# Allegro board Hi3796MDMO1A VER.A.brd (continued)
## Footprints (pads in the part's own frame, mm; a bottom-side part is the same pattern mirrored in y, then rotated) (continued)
SEN3-100C
  rect 1.27x1.27 hole 0.813: 1(-2.54,0)
  round 1.27 hole 0.813: 2(0,0) 3(2.54,0)
SGM8903
  rect 0.356x1.524 smd: 1(-1.95,-2.921) 2(-1.3,-2.921) 3(-0.65,-2.921) 4(0,-2.921) 5(0.65,-2.921) 6(1.3,-2.921) 7(1.95,-2.921) 8(1.95,2.921) 9(1.3,2.921) 10(0.65,2.921) 11(0,2.921) 12(-0.65,2.921) 13(-1.3,2.921) 14(-1.95,2.921)
SIP-1P
  round 1.651 hole 0.914: 1(0,0)
SIP-6P-100
  rect 1.524x1.524 hole 1.016: 1(6.25,0)
  round 1.524 hole 1.016: 2(3.75,0) 3(1.25,0) 4(-1.25,0) 5(-3.75,0) 6(-6.25,0)
SL0402
  rect 0.483x0.508 smd: 1(-0.394,0) 2(0.394,0)
SL0603
  rect 0.711x0.813 smd: 1(-0.74,0) 2(0.74,0)
SL0805
  rect 0.94x1.27 smd: 1(-0.851,0) 2(0.851,0)
SL1210
  rect 1.295x2.413 smd: 1(-1.346,0) 2(1.346,0)
SOP14-50-150
  rect 0.635x1.905 smd: 1(-3.81,-2.667) 2(-2.54,-2.667) 3(-1.27,-2.667) 4(0,-2.667) 5(1.27,-2.667) 6(2.54,-2.667) 7(3.81,-2.667) 8(3.81,2.667) 9(2.54,2.667) 10(1.27,2.667) 11(0,2.667) 12(-1.27,2.667) 13(-2.54,2.667) 14(-3.81,2.667)
SOP48-20-720B
  rect 0.254x1.473 smd: 1(-5.75,-9.802) 2(-5.25,-9.802) 3(-4.75,-9.802) 4(-4.25,-9.802) 5(-3.75,-9.802) 6(-3.25,-9.802) 7(-2.75,-9.802) 8(-2.25,-9.802) 9(-1.75,-9.802) 10(-1.25,-9.802) 11(-0.75,-9.802) 12(-0.25,-9.802) 13(0.25,-9.802) 14(0.75,-9.802) 15(1.25,-9.802) 16(1.75,-9.802) 17(2.25,-9.802) 18(2.75,-9.802) 19(3.25,-9.802) 20(3.75,-9.802) 21(4.25,-9.802) 22(4.75,-9.802) 23(5.25,-9.802) 24(5.75,-9.802) 25(5.75,9.802) 26(5.25,9.802) 27(4.75,9.802) 28(4.25,9.802) 29(3.75,9.802) 30(3.25,9.802) 31(2.75,9.802) 32(2.25,9.802) 33(1.75,9.802) 34(1.25,9.802) 35(0.75,9.802) 36(0.25,9.802) 37(-0.25,9.802) 38(-0.75,9.802) 39(-1.25,9.802) 40(-1.75,9.802) 41(-2.25,9.802) 42(-2.75,9.802) 43(-3.25,9.802) 44(-3.75,9.802) 45(-4.25,9.802) 46(-4.75,9.802) 47(-5.25,9.802) 48(-5.75,9.802)
SOT23
  rect 1.016x1.27 smd: 1(-1.016,-1.143) 2(1.016,-1.143) 3(0,1.143)
SOT23-5
  rect 0.711x1.016 smd: 1(-0.95,-1.3) 2(0,-1.3) 3(0.95,-1.3) 4(0.95,1.3) 5(-0.95,1.3)
SOT23_5
  rect 0.635x1.27 smd: 1(-0.95,-1.2) 2(0,-1.2) 3(0.95,-1.2) 4(0.95,1.2) 5(-0.95,1.2)
SOT23_6
  rect 0.635x1.397 smd: 1(-0.95,-1.2) 2(0,-1.2) 3(0.95,-1.2) 4(0.95,1.2) 5(0,1.2) 6(-0.95,1.2)
SOT23A-6L
  rect 0.635x1.27 smd: 1(-0.95,-1.25) 2(0,-1.25) 3(0.95,-1.25) 4(0.95,1.25) 5(0,1.25) 6(-0.95,1.25)
SOT223A
  rect 1.016x2.032 smd: 1(-2.286,-3.15) 2(0,-3.15) 3(2.286,-3.15)
  rect 3.302x2.032 smd: 4(0,3.15)
SPSW6-T
  rect 1.829x1.118 smd: 1(-3.1,1.85) 2(3.1,1.85) 3(-3.1,-1.85) 4(3.1,-1.85)
  rect 1.397x0.61 smd: 5(0,2.5) 6(0,-2.5)
SR0402
  rect 0.508x0.508 smd: 1(-0.406,0) 2(0.406,0)
SR0603
  rect 0.711x0.813 smd: 1(-0.737,0) 2(0.737,0)
SR0805
  rect 0.838x1.143 smd: 1(-0.927,0) 2(0.927,0)
SR1206
  rect 1.295x1.6 smd: 1(-1.346,0) 2(1.346,0)
STFM16-50-285
  rect 0.635x1.905 smd: 1(-4.445,-4.381) 2(-3.175,-4.381) 3(-1.905,-4.381) 4(-0.635,-4.381) 5(0.635,-4.381) 6(1.905,-4.381) 7(3.175,-4.381) 8(4.445,-4.381) 9(4.445,4.381) 10(3.175,4.381) 11(1.905,4.381) 12(0.635,4.381) 13(-0.635,4.381) 14(-1.905,4.381) 15(-3.175,4.381) 16(-4.445,4.381)
SWPA4020S
  rect 1.905x3.683 smd: 1(-1.55,0) 2(1.55,0)
SWPA4030S
  rect 1.905x3.683 smd: 1(-1.55,0) 2(1.55,0)
SWPA5040S
  rect 1.397x4.191 smd: 1(-1.85,0) 2(1.85,0)
SX2-1205
  rect 4.826x1.524 smd: 1(-4.85,0) 2(4.85,0)
TO-252
  rect 1.27x2.032 smd: 1(-2.285,-3.375) 2(0,-3.375) 3(2.285,-3.375)
  rect 5.715x5.842 smd: 4(0,3.375)
TSSOP16EP
  rect 0.356x1.651 smd: 1(-2.275,-2.9) 2(-1.625,-2.9) 3(-0.975,-2.9) 4(-0.325,-2.9) 5(0.325,-2.9) 6(0.975,-2.9) 7(1.625,-2.9) 8(2.275,-2.9) 9(2.275,2.9) 10(1.625,2.9) 11(0.975,2.9) 12(0.325,2.9) 13(-0.325,2.9) 14(-0.975,2.9) 15(-1.625,2.9) 16(-2.275,2.9)
  rect 4.191x3.302 smd: 17(0,0)
TSW4-RG-C
  round 1.524 hole 1.016: 1(0,0) 2(4.5,0)
  round 2.032 hole 1.321: 3(-1.25,2.5) 4(5.75,2.5)
unnamed#2
  round 1.016 hole 1.016 unplated: (-3,1.13) (-1.5,1.13) (0,1.13) (1.5,1.13) (3,1.13)
USB3_0_9P_DIP_MAINSUPER
  round 1.245 hole 0.762: 1(0,0) 2(2.5,0) 3(4.5,0) 4(7,0) 5(7.5,1.5) 6(5.5,1.5) 7(3.5,1.5) 8(1.5,1.5) 9(-0.5,1.5)
  round 2.896 hole 2.413: 10(-3.07,-2) 11(10.07,-2)
USB4-1415
  rect 1.27x1.524 hole 1.016: 1(0,0)
  oval 1.27x1.524 hole 1.016: 2(2.5,0) 3(4.5,0) 4(7,0)
  round 3.048 hole 2.286: 5(-3.07,-2.71) 6(10.07,-2.71)
VAF6-1107
  round 1.016 hole 1.016 unplated: (1.7,2.3) (8.5,2.3)
  round 0 smd: 1(4.503,2.3)
  rect 2.159x1.626 hole 1.321x0.61: 2(0,0)
  oval 2.159x1.626 hole 1.321x0.61: 3(3,0)
  oval 2.337x1.626 hole 1.321x0.61: 4(7,0.2) 5(8.6,4.6) 6(0,5.6)
WBC0104-49T
  oval 0.762x1.143 hole 0.508: 1(0,0) 2(1.25,0) 3(2.5,0) 4(3.75,0)
WBC0119-20R-A
  round 1.092 hole 1.092 unplated: (-2.5,2.745) (2.5,2.745)
  rect 0.254x2.591 smd: 1(4.5,5.155) 2(4,5.155) 3(3.5,5.155) 4(3,5.155) 5(2.5,5.155) 6(2,5.155) 7(1.5,5.155) 8(1,5.155) 9(0.5,5.155) 10(0,5.155) 11(-0.5,5.155) 12(-1,5.155) 13(-1.5,5.155) 14(-2,5.155) 15(-2.5,5.155) 16(-3,5.155) 17(-3.5,5.155) 18(-4,5.155) 19(-4.5,5.155)
  oval 1.524x3.302 hole 0.914x2.667: 20(-7.25,4.395) 21(7.25,4.395)
  oval 1.524x2.794 hole 0.914x2.083: 22(-7.25,-1.565) 23(7.25,-1.565)
X288
  rect 1.651x1.27 smd: 1(-1.15,-0.85) 2(1.15,-0.85) 3(1.15,0.85) 4(-1.15,0.85)

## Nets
1V1_CORE: C19.1 C51.1 C82.2 C90.1 C107.1 C120.1 C121.1 C127.1 C128.1 C173.1 C189.1 C192.1 C193.1 L3.2 LB11.1 LB12.2 LB21.1 LB31.1 R101.2 U10.K14 U10.K15 U10.K16 U10.K17 U10.L14 U10.L15 U10.M14 U10.M15 U10.N14 U10.N15 U10.P14 U10.P15 U10.R11 U10.R14 U10.R15 U10.T11 U10.T14 U10.T15 U10.U11 U10.U12 U10.U13 U10.U14 U10.U15 U10.V11 U10.V12 U10.V13 U10.V14 U10.V15 U10.V16
1V1_CPU: C31.1 C35.1 C41.1 C76.2 C116.1 C132.1 C135.1 C138.1 C161.1 C242.1 C243.1 C257.1 L4.2 R53.2 U10.L21 U10.M19 U10.M21 U10.M22 U10.N18 U10.N19 U10.N22 U10.P18 U10.P19 U10.P22 U10.R19 U10.R21
1V2_ADC_S: C125.1 C209.1 LB13.2 U2.33
1V2_APLL_S: C126.1 C210.1 LB15.2 U2.28
1V2_DVDD_S: C109.1 C110.1 C113.1 C117.1 C205.1 LB10.2 U2.7 U2.17 U2.25 U2.42
1V5_DDR3: C20.1 C34.1 C42.1 C68.1 C84.2 C94.1 C96.1 C97.1 C98.1 C99.1 C100.1 C101.1 C102.1 C106.1 C137.1 C152.1 C179.1 C180.1 C203.1 C206.1 C207.1 C208.1 C211.1 C212.1 C213.1 C214.1 C215.1 C216.1 C218.1 C219.1 C220.1 C222.1 C223.1 C227.1 C228.1 C229.1 C230.1 C232.1 C233.1 C237.1 C238.1 C239.1 C240.1 C258.1 C315.1 C319.1 L2.2 R26.2 R54.1 R78.1 R120.2 R158.1 R161.1 U3.A1 U3.A8 U3.B2 U3.C1 U3.C9 U3.D2 U3.D9 U3.E9 U3.F1 U3.G7 U3.H2 U3.H9 U3.K2 U3.K8 U3.N1 U3.N9 U3.R1 U3.R9 U6.A1 U6.A8 U6.B2 U6.C1 U6.C9 U6.D2 U6.D9 U6.E9 U6.F1 U6.G7 U6.H2 U6.H9 U6.K2 U6.K8 U6.N1 U6.N9 U6.R1 U6.R9 U10.AA7 U10.AB6 U10.AB7 U10.AB8 U10.AB9 U10.AB10 U10.AB11 U10.AB12 U10.AB13 U10.AB14 U10.AB15 U10.AC5 U10.AC6 U10.AC7 U10.AC8 U10.AC12 U10.AD4 U10.AD5 U10.AD6 U10.AD7 U10.AE4 U10.AE5 U10.AE6 U10.N7 U10.N9 U10.P7 U10.P9 U10.R6 U10.R7 U10.T7 U10.U7 U10.V7 U10.W7 U10.W9 U10.Y7 U10.Y9 U10.Y11 U10.Y12
3V3: C13.1 C67.1 C108.1 C112.2 C187.1 C191.1 J18.4 L5.2 Q13.2 R34.1 R41.1 R42.2 R88.2 R100.2 R122.1 R129.1 R135.1 R136.2 R140.2 R147.1 R178.1 U10.AD23 U10.AD24
3V3_AVDD_S: C86.1 C201.1 LB5.2 R69.1 U2.30
3V3_DVDD_S: C73.1 C74.1 C75.1 C81.1 C200.1 LB4.2 R103.2 U2.4 U2.11 U2.19 U2.45
3V3_MOS: C15.1 C88.1 C89.1 C92.1 C157.1 C197.1 C198.1 C199.1 C202.1 C245.1 C348.1 D9.2 D12.2 D14.2 J7.5 J25.10 J25.12 L21.1 LB1.2 LB3.1 LB4.1 LB5.1 LB7.2 LB8.2 LB14.1 LB17.1 LB18.1 LB20.1 LB22.1 LB35.1 Q13.3 Q14.1 Q15.2 R35.1 R65.1 R66.1 R77.1 R91.2 R96.2 R104.1 R108.1 R109.1 R116.2 R125.2 R155.1 R218.1 R219.1 R267.1 R271.1 U10.AA24 U10.AB24 U10.E13 U10.E14 U10.E19 U10.G5 U10.H24 U10.K24 U10.L24 U10.Y24 U12.3
3V3_MOS_FLASH: C22.1 C36.1 C47.1 C48.1 C93.1 C142.1 C143.1 C162.1 C323.1 C324.1 D14.1 R12.1 R25.1 R29.1 R58.1 R109.2 R111.1 R176.1 R177.1 R188.1 R189.1 R202.1 R203.1 R212.1 R215.1 U19.1(TP-1) U19.12(TP-12) U19.24(TP-24) U19.34(TP-34) U19.37(TP-37) U22.AA3 U22.AA5 U22.K6 U22.M6 U22.N5 U22.T10 U22.U9 U22.W4 U22.Y4
3V3_RF: C57.1 C144.1 C169.2 C195.2 C296.1 L21.2 R112.2 U14.2(TP-2) U14.4(TP-4) U34.23 U34.28
3V3_SD: C28.1 C61.1 J13.4 Q15.3 R210.1
3V3_WIFI: C60.1 C196.1 LB3.2 U7.5
5V0: C2.1 C4.1 C6.1 C25.1 C26.1 C27.1 C46.1 C53.1 C59.1 C65.1 C69.1 C83.1 C114.1 C184.1 L8.2 Q8.2 R6.1 R48.1 R144.1 R191.2 U1.4 U11.4 U13.4 U15.4
5V0_MOS: C50.1 C56.1 C87.2 C347.1 D13.2 J7.3 LB33.1 LB47.1 LB49.1 Q8.3 R113.2 R179.1 R220.2 U16.1 U24.14 U26.1
5V0_MOS_HDMI: C150.1 D13.1 J26.18 R186.2 R187.2 U4.5
5V0_SPDIF: C159.1 LB49.2 U9.2(TP-2)
12V0_MOS: C63.1 C136.1 C183.1 J7.1 L7.1 Q3.3 R117.1 R121.1 U17.3
12V0_PWR: C44.1 C91.1 C111.1 C133.1 C160.1 LB6.2 Q3.2 R95.1 R98.1 R110.1 U18.3
AVDD11_PLL012: C12.1 C185.1 LB21.2 U10.U18 U10.U19
AVDD11_USB3: C16.1 C119.1 LB11.2 U10.AA19 U10.Y18 U10.Y19
AVDD33_ADAC: C188.1 LB35.2 U10.E22
AVDD33_PLL01: C14.1 C141.1 LB22.2 U10.W21 U10.Y22
AVDD33_USB2: C3.1 LB17.2 U10.U24
AVDD33_USB3: C18.1 LB18.2 U10.AD20 U10.AD21
DVDD11_LDO1_OUT: C255.2 U10.AA21
GND: C1.2 C2.2 C3.2 C4.2 C5.2 C7.2 C8.2 C9.2 C10.2 C11.2 C12.2 C13.2 C14.2 C15.2 C16.2 C17.2 C18.2 C19.2 C20.2 C21.2 C22.2 C23.2 C24.2 C25.2 C26.2 C27.2 C28.2 C29.2 C30.2 C31.2 C33.1 C34.2 C35.2 C36.2 C37.2 C38.2 C39.2 C40.2 C41.2 C42.2 C43.2 C44.2 C45.2 C46.2 C47.2 C48.2 C49.2 C50.2 C51.2 C52.2 C53.2 C56.2 C57.2 C58.2 C59.2 C60.2 C61.2 C62.2 C63.2 C65.2 C66.2 C67.2 C68.2 C69.2 C71.2 C72.2 C73.2 C74.2 C75.2 C77.2 C78.2 C79.2 C81.2 C83.2 C85.2 C86.2 C87.1 C88.2 C89.2 C90.2 C91.2 C92.2 C93.2 C94.2 C95.2 C96.2 C97.2 C98.2 C99.2 C100.2 C101.2 C102.2 C103.2 C104.2 C105.2 C106.2 C107.2 C108.2 C109.2 C110.2 C111.2 C113.2 C114.2 C115.2 C116.2 C117.2 C118.1 C119.2 C120.2 C121.2 C122.2 C123.2 C124.2 C125.2 C126.2 C127.2 C128.2 C130.2 C131.2 C132.2 C134.2 C135.2 C136.2 C137.2 C138.2 C140.2 C141.2 C142.2 C143.2 C144.2 C145.2 C146.2 C147.2 C148.2 C149.2 C150.2 C151.2 C152.2 C153.2 C154.2 C158.2 C159.2 C160.2 C161.2 C162.2 C163.1 C164.2 C165.2 C166.2 C167.2 C168.1 C169.1 C170.2 C171.1 C172.2 C173.2 C174.2 C176.2 C177.2 C179.2 C180.2 C181.2 C182.2 C183.2 C184.2 C185.2 C187.2 C188.2 C189.2 C190.2 C191.2 C192.2 C193.2 C194.2 C195.1 C196.2 C197.2 C198.2 C199.2 C200.2 C201.2 C202.2 C203.2 C204.2 C205.2 C206.2 C209.2 C210.2 C211.2 C212.2 C213.2 C214.2 C215.2 C216.2 C217.2 C218.2 C219.2 C220.2 C221.2 C225.1 C226.2 C227.2 C228.2 C229.2 C230.2 C232.2 C233.2 C237.2 C238.2 C239.2 C240.2 C241.2 C242.2 C243.2 C244.2 C245.2 C246.2 C248.2 C250.1 C251.2 C255.1 C257.2 C258.2 C264.2 C270.2 C271.2 C281.2 C287.2 C288.2 C289.2 C296.2 C297.2 C304.1 C305.1 C308.2 C310.2 C313.2 C314.2 C315.2 C316.2 C317.2 C319.2 C320.2 C323.2 C324.2 C334.2 C336.2 C339.2 C341.1 C342.1 C343.1 C344.1 C347.2 C348.2 C353.2 C354.2 C363.2 C364.2 C365.2 C414.2 C487.1 C489.2 C490.2 C491.2 C531.2 C532.2 C534.2 C535.2 C536.2 C537.2 C538.2 C545.2 D3.2 D4.2 D5.2 D6.2 D9.1 D10.2 D11.1 D15.2 J1.4 J3.1 J4.1 J5.1 J6.4 J6.5 J6.6 J7.2 J7.4 J7.6 J7.7 J7.8 J7.18 J7.20 J9.4 J9.5 J9.6 J12.4 J12.7 J12.10 J12.11 J13.6 J13.10 J13.11 J13.12 J13.13 J13.14 J13.15 J14.1 J14.2 J14.3 J14.4 J16.3 J16.4 J16.5 J16.6 J16.7 J16.8 J18.1 J26.2 J26.5 J26.8 J26.11 J26.17 J26.20 J26.21 J26.22 J26.23 J34.5 L16.1 LB9.2 LED1.2 M20.1 M20.2 M20.3 M20.4 M20.5 M20.6 M20.7 M20.8 M21.1 M21.2 M21.3 M21.4 M21.5 M21.6 M21.7 M21.8 M22.1 M22.2 M22.3 M22.4 M22.5 M22.6 M22.7 M22.8 M23.1 M23.2 M23.3 M23.4 M23.5 M23.6 M23.7 M23.8 Q2.2 Q4.2 Q5.2 Q6.2 Q7.2 Q9.2 R2.2 R3.2 R4.2 R8.1 R9.2 R32.1 R43.2 R44.1 R45.2 R46.1 R47.2 R52.2 R55.2 R56.1 R57.2 R59.2 R64.2 R71.1 R72.2 R82.1 R83.2 R84.2 R85.2 R86.2 R87.1 R89.2 R92.2 R94.2 R99.1 R102.1 R105.2 R106.1 R107.2 R110.2 R111.2 R115.1 R123.2 R124.1 R126.1 R130.1 R131.2 R138.2 R141.2 R145.2 R146.2 R148.2 R149.2 R159.2 R160.2 R173.2 R183.2 R210.2 R229.2 R268.2 R269.2 R270.2 S9.2 S9.3 S9.4 S10.3 S10.4 S10.5 S10.6 U1.2 U2.29 U2.34 U2.47 U2.49 U3.A9 U3.B1 U3.B3 U3.B9 U3.D1 U3.D8 U3.E1 U3.E2 U3.E8 U3.F9 U3.G1 U3.G8 U3.G9 U3.J2 U3.J8 U3.M1 U3.M9 U3.P1 U3.P9 U3.T1 U3.T9 U4.2 U5.1 U5.4 U5.10 U5.14 U6.A9 U6.B1 U6.B3 U6.B9 U6.D1 U6.D8 U6.E1 U6.E2 U6.E8 U6.F9 U6.G1 U6.G8 U6.G9 U6.J2 U6.J8 U6.M1 U6.M9 U6.P1 U6.P9 U6.T1 U6.T9 U7.2 U8.3 U8.8 U9.3(TP-3) U10.A1 U10.A2 U10.A3 U10.A28 U10.AA1 U10.AA6 U10.AA18 U10.AA20 U10.AB2 U10.AB5 U10.AB16 U10.AB25 U10.AB27 U10.AC4 U10.AC9 U10.AC10 U10.AC11 U10.AC13 U10.AC14 U10.AC15 U10.AC16 U10.AC24 U10.AD3 U10.AD8 U10.AD9 U10.AD12 U10.AD14 U10.AD16 U10.AD17 U10.AD19 U10.AD22 U10.AD25 U10.AD26 U10.AE1 U10.AE3 U10.AE7 U10.AE8 U10.AE10 U10.AE18 U10.AE19 U10.AE21 U10.AE22 U10.AE23 U10.AE24 U10.AE25 U10.AE26 U10.AF2 U10.AF3 U10.AF4 U10.AF9 U10.AF14 U10.AF15 U10.AF16 U10.AF18 U10.AF19 U10.AF21 U10.AF22 U10.AF25 U10.AG1 U10.AG2 U10.AG5 U10.AG7 U10.AG11 U10.AG13 U10.AG28 U10.AH1 U10.AH2 U10.AH4 U10.AH6 U10.AH10 U10.AH12 U10.AH27 U10.AH28 U10.B2 U10.B3 U10.B4 U10.B14 U10.B25 U10.B26 U10.B27 U10.C3 U10.C4 U10.C6 U10.C7 U10.C8 U10.C10 U10.C14 U10.C16 U10.C18 U10.C19 U10.C20 U10.C22 U10.C24 U10.C25 U10.C26 U10.D4 U10.D6 U10.D7 U10.D8 U10.D10 U10.D14 U10.D16 U10.D18 U10.D19 U10.D20 U10.D22 U10.D24 U10.D25 U10.E2 U10.E4 U10.E5 U10.E8 U10.E9 U10.E11 U10.E12 U10.E15 U10.E18 U10.E20 U10.E21 U10.E23 U10.E24 U10.E25 U10.E26 U10.F1 U10.F3 U10.F4 U10.F5 U10.F25 U10.G4 U10.G8 U10.G12 U10.G13 U10.G14 U10.G17 U10.G19 U10.G21 U10.G24 U10.G25 U10.G26 U10.H1 U10.H2 U10.H4 U10.H5 U10.H12 U10.H13 U10.H14 U10.H17 U10.H18 U10.H21 U10.H22 U10.H25 U10.J3 U10.J4 U10.J5 U10.J21 U10.J22 U10.J24 U10.J25 U10.J26 U10.K3 U10.K11 U10.K13 U10.K18 U10.K19 U10.K21 U10.K22 U10.K25 U10.K26 U10.K27 U10.L1 U10.L2 U10.L3 U10.L4 U10.L5 U10.L11 U10.L12 U10.L13 U10.L16 U10.L17 U10.L18 U10.L19 U10.L22 U10.L25 U10.L26 U10.M3 U10.M4 U10.M5 U10.M6 U10.M11 U10.M12 U10.M13 U10.M16 U10.M17 U10.M18 U10.M24 U10.M25 U10.N3 U10.N6 U10.N11 U10.N12 U10.N13 U10.N16 U10.N17 U10.N24 U10.N25 U10.N26 U10.P2 U10.P6 U10.P11 U10.P12 U10.P13 U10.P16 U10.P17 U10.P24 U10.P25 U10.P26 U10.R1 U10.R3 U10.R5 U10.R9 U10.R12 U10.R13 U10.R16 U10.R17 U10.R18 U10.R22 U10.R24 U10.R26 U10.T3 U10.T4 U10.T6 U10.T12 U10.T13 U10.T16 U10.T17 U10.T18 U10.T19 U10.T22 U10.T24 U10.T25 U10.T26 U10.U6 U10.U9 U10.U16 U10.U17 U10.U21 U10.U22 U10.U25 U10.V2 U10.V3 U10.V5 U10.V6 U10.V9 U10.V17 U10.V18 U10.V19 U10.V21 U10.V24 U10.V25 U10.W1 U10.W5 U10.W6 U10.W22 U10.W24 U10.Y2 U10.Y4 U10.Y6 U10.Y10 U10.Y13 U10.Y15 U10.Y21 U10.Y25 U10.Y27 U11.2 U13.2 U15.2 U16.2 U17.1 U17.16 U17.17 U18.1 U19.2(TP-2) U19.13(TP-13) U19.23(TP-23) U19.25(TP-25) U19.36(TP-36) U19.48(TP-48) U22.AA4 U22.AA6 U22.K4 U22.M7 U22.P5 U22.R10 U22.U8 U22.Y2 U22.Y5 U23.3 U23.8 U24.2 U24.7 U26.2 U34.29 X2.2 X2.4
VCC_SCI: C29.1 C39.1 C40.1 J1.1 R124.2 R243.1 R302.2
VDD_AUDIO: C158.1 C320.1 R139.2 R174.1 R179.2 U5.9
3136_ADDR0: R3.1 U2.39
3136_ADDR1: R103.1 U2.38
3136_DISEQC_IN: Q6.3 R51.1 R116.1 U2.13
3136_DISEQC_OUT: R123.1 U2.12 U17.9
3136_FUNC_SEL: R4.1 U2.14
3136_HV_SEL: U2.18 U17.8
3136_I2C_SCL: C221.1 R108.2 U2.41 U10.D26
3136_I2C_SDA: C217.1 R104.2 U2.40 U10.C27
3136_IOUT_N: C307.2 U2.32
3136_IOUT_P: C303.2 U2.31
3136_LNB_EN: U2.21 U17.5
3136_QOUT_N: C186.2 U2.35
3136_QOUT_P: C306.2 U2.36
3136_RF_AGC: C37.1 R60.1 R127.2
3136_RSTN: C38.1 R83.1 U2.15 U10.C28
3136_TS_CLK: R10.2 U2.46
3136_TS_OUT0: R13.2 U2.48
3136_TS_SYNC: R226.2 U2.43
3136_TS_VAL: C176.1 R5.2 U2.44
3136_XIN: C172.1 R24.1 U2.23 X1.2
3136_XOUT: C174.1 R24.2 U2.22 X1.1
AC2012_SCL_T: R61.2 R65.2 U2.27
AC2012_SDA_T: R62.2 R66.2 U2.26
ADAC_VOUTL: C350.2 R138.1 U10.D23
ADAC_VOUTR: C351.1 R183.1 U10.C23
ADAC_VREF: C250.2 U10.G18
AUDIO_L: C339.1 J34.3 R119.2
AUDIO_R: C140.1 J34.2 R74.1
CORE_CTRL: R23.2 U10.E27
CPU_CTRL: R21.2 U10.E28
CVBS: C79.1 C80.1 L6.1 R9.1 U10.A25
CVBS_OUT: C17.1 C80.2 D9.3 J34.4 L6.2
DDR_ADDR0: U3.N3 U6.N3 U10.AF13
DDR_ADDR1: U3.P7 U6.P7 U10.AE12
DDR_ADDR2: U3.P3 U6.P3 U10.AD15
DDR_ADDR3: U3.N2 U6.N2 U10.AH15
DDR_ADDR4: U3.P8 U6.P8 U10.AD13
DDR_ADDR5: U3.P2 U6.P2 U10.AE16
DDR_ADDR6: U3.R8 U6.R8 U10.AF11
DDR_ADDR7: U3.R2 U6.R2 U10.AG15
DDR_ADDR8: U3.T8 U6.T8 U10.AG12
DDR_ADDR9: U3.R3 U6.R3 U10.AE17
DDR_ADDR10: U3.L7 U6.L7 U10.AE9
DDR_ADDR11: U3.R7 U6.R7 U10.AG10
DDR_ADDR12: U3.N7 U6.N7 U10.AE11
DDR_ADDR13: U3.T3 U6.T3 U10.AF17
DDR_ADDR14: U3.T7 U6.T7 U10.AF12
DDR_ADDR15: U3.M7 U6.M7 U10.AD11
DDR_BA0: U3.M2 U6.M2 U10.AH16
DDR_BA1: U3.N8 U6.N8 U10.AF10
DDR_BA2: U3.M3 U6.M3 U10.AE13
DDR_CASN: U3.K3 U6.K3 U10.AE15
DDR_CKE: R130.2 U3.K9 U6.K9 U10.AD10
DDR_CLK1N: R11.2 R15.2 R37.1 U3.K7 U6.K7
DDR_CLK1P: R11.1 R15.1 R36.1 U3.J7 U6.J7
DDR_CSN: U3.L2 U6.L2 U10.AH13
DDR_DM0: U3.E7 U10.R4
DDR_DM1: U3.D3 U10.T5
DDR_DM2: U6.E7 U10.AF1
DDR_DM3: U6.D3 U10.AE2
DDR_DQ0: U3.E3 U10.N4
DDR_DQ1: U3.F7 U10.V1
DDR_DQ2: U3.F2 U10.N1
DDR_DQ3: U3.F8 U10.W3
DDR_DQ4: U3.H3 U10.N5
DDR_DQ5: U3.H8 U10.Y3
DDR_DQ6: U3.G2 U10.N2
DDR_DQ7: U3.H7 U10.W2
DDR_DQ8: U3.D7 U10.U4
DDR_DQ9: U3.C3 U10.R2
DDR_DQ10: U3.C8 U10.U5
DDR_DQ11: U3.C2 U10.P3
DDR_DQ12: U3.A7 U10.V4
DDR_DQ13: U3.A2 U10.P4
DDR_DQ14: U3.B8 U10.W4
DDR_DQ15: U3.A3 U10.P5
DDR_DQ16: U6.E3 U10.AA5
DDR_DQ17: U6.F7 U10.AF6
DDR_DQ18: U6.F2 U10.AA2
DDR_DQ19: U6.F8 U10.AG6
DDR_DQ20: U6.H3 U10.Y5
DDR_DQ21: U6.H8 U10.AH7
DDR_DQ22: U6.G2 U10.AA3
DDR_DQ23: U6.H7 U10.AF7
DDR_DQ24: U6.D7 U10.AF5
DDR_DQ25: U6.C3 U10.AB1
DDR_DQ26: U6.C8 U10.AG4
DDR_DQ27: U6.C2 U10.AB3
DDR_DQ28: U6.A7 U10.AH3
DDR_DQ29: U6.A2 U10.AA4
DDR_DQ30: U6.B8 U10.AG3
DDR_DQ31: U6.A3 U10.AB4
DDR_DQS0N: U3.G3 U10.T1
DDR_DQS0P: U3.F3 U10.T2
DDR_DQS1N: U3.B7 U10.U3
DDR_DQS1P: U3.C7 U10.U2
DDR_DQS2N: U6.G3 U10.AC2
DDR_DQS2P: U6.F3 U10.AC3
DDR_DQS3N: U6.B7 U10.AD2
DDR_DQS3P: U6.C7 U10.AD1
DDR_ODT: U3.K1 U6.K1 U10.AG16
DDR_PLL: C11.1 C264.1 C270.1 LB7.1 U10.T9 U10.Y14
DDR_RASN: U3.J3 U6.J3 U10.AG17
DDR_RESETN: C313.1 C314.1 R26.1 U3.T2 U6.T2 U10.AG14
DDR_VREF_CA_A: C207.2 C289.1 R158.2 R159.1 U3.M8
DDR_VREF_CA_B: C222.2 C310.1 R107.1 R161.2 U6.M8
DDR_VREF_DQ_A: C208.2 C271.1 R54.2 R160.1 U3.H1
DDR_VREF_DQ_B: C223.2 C308.1 R78.2 R84.1 U6.H1
DDR_WEN: U3.L3 U6.L3 U10.AE14
DEMOD0_RESTN: J7.10 U10.L28
DEMOD0_SCL: J7.23 U10.G27
DEMOD0_SDA: J7.24 U10.G28
FE_1V1: C248.1 U10.K12
FE_3V3: C7.1 LB8.1 U10.E6 U10.E7
FE_REXT: R173.1 U10.G9
FUNC_SEL: R42.1 U10.AF26
HDMI_TX0N: J26.9 U8.2 U8.9 U10.D17
HDMI_TX0P: J26.7 U8.1 U8.10 U10.C17
HDMI_TX1N: J26.6 U10.B16 U23.5 U23.6
HDMI_TX1P: J26.4 U10.A16 U23.4 U23.7
HDMI_TX2N: J26.3 U10.D15 U23.2 U23.9
HDMI_TX2P: J26.1 U10.C15 U23.1 U23.10
HDMI_TX_1V1: C95.1 C164.1 C251.1 C281.1 LB12.1 U10.G16 U10.H16
HDMI_TX_3V3: C77.1 C122.1 LB1.1 U10.E16 U10.E17
HDMI_TX_CEC: J26.13 R184.2 U4.3 U10.A20
HDMI_TX_HOTPLUG: C149.1 J26.19 R8.2 U4.4 U10.D21
HDMI_TX_SCL: J26.15 R186.1 U4.1 U10.B20
HDMI_TX_SDA: J26.16 R187.1 U4.6 U10.C21
HDMI_TXCN: J26.12 U8.5 U8.6 U10.B18
HDMI_TXCP: J26.10 U8.4 U8.7 U10.A18
I2S0_BCLK: U10.D12
I2S0_DIN0: U10.D11
I2S0_DOUT0: U10.A10
I2S0_MCLK: U10.C11
I2S0_WS: U10.B10
IR_IN: D3.1 R140.1 U10.AG24
JTAG_SEL: R96.1 U10.F26
LED: U7.1
LED0_BASE: R67.2 R219.2 U10.C2
LED0_LINK_ACT: R185.2 R218.2 U10.B1
LED_CLK: R22.1 R57.1 R147.2 U10.AH23
LED_DATA: R31.1 R122.2 R148.1 U10.AG23
LED_KEY0: C21.1 R41.2 S9.1 U10.AF23
LNB_PWR: C58.1 C64.1 C78.1 C104.1 C155.2 C170.1 D17.2 D27.1 J16.2
LNB_PWR_B: C166.1 C287.1 C288.1 D27.2 R166.2
LOOPTHROUGH: C283.1 J16.1 R166.1
MUTE_CTRL: R90.1 U10.A22
NF_ALE_EMMC_PWREN: U10.W26 U19.17(TP-17)
NF_CLE: U10.V26 U19.16(TP-16)
NF_CSN0_EMMC_CMD: R212.2 U10.V28 U19.9(TP-9) U22.W5
NF_DQ0_EMMC_D0: R189.2 U10.Y28 U19.29(TP-29) U22.H3
NF_DQ1_EMMC_D1: R12.2 U10.Y26 U19.30(TP-30) U22.H4
NF_DQ2_EMMC_D2: R29.2 U10.AA26 U19.31(TP-31) U22.H5
NF_DQ3_EMMC_D3: R58.2 U10.AA25 U19.32(TP-32) U22.J2
NF_DQ4_EMMC_D4: R176.2 U10.AB28 U19.41(TP-41) U22.J3
NF_DQ5_EMMC_D5: R177.2 U10.AB26 U19.42(TP-42) U22.J4
NF_DQ6_EMMC_D6: R188.2 U10.AC26 U19.43(TP-43) U22.J5
NF_DQ7_EMMC_D7_BOOT_SEL0: R86.1 R202.2 U10.AC25 U19.44(TP-44) U22.J6
NF_RDY0_EMMC_RST: C115.1 R203.2 U10.U26 U19.7(TP-7) U22.U5
NF_REN_EMMC_CLK: U10.W25 U19.8(TP-8) U22.W6
NF_WEN_EMMC_DET: R56.2 U10.V27 U19.18(TP-18)
NF_WP: R89.1 R215.2 U19.19(TP-19)
REG2OUT: C130.1 C131.1 C225.2 C414.1 U34.1 U34.2 U34.5 U34.10 U34.25
RX+_PHY0: R50.1 U10.B6 U27.3 U27.6
RX-_PHY0: R18.1 U10.A6 U27.4 U27.5
SDIO0_CARD_DETECT: J13.9 R155.2 U10.J2
SDIO0_CCLK_OUT: J13.5 R16.1
SDIO0_CCMD: J13.3 R153.2 U10.F2
SDIO0_CDATA0: J13.7 R152.2 U10.E3
SDIO0_CDATA1: J13.8 R151.2 U10.D3
SDIO0_CDATA2: J13.1 R154.2 U10.H3
SDIO0_CDATA3: J13.2 R156.2 U10.G3
SDIO0_CWPR: R82.2 U10.C1
SDIO0_PWREN: R76.1 R149.1 U10.J1
SDIO_3318: C62.1 C118.2 R151.1 R152.1 R153.1 R154.1 R156.1 U10.K4 U10.K5
SIM0_CARD_I/O: C489.1 J1.5 Q14.3 R243.2
SIM0_CLK: R168.1 U10.AH26
SIM0_CLK_OUT: J1.2 R269.1 U24.8
SIM0_DATA: R38.1 U10.AG25
SIM0_DET: R39.1 U10.AH25
SIM0_PWREN: R271.2 U10.AG26 U24.1 U24.4 U24.10 U24.12
SIM0_PWREN_CTL: R242.1 U24.3
SIM0_RST: U10.AF24 U24.5
SIM0_RST_OUT: C491.1 J1.3 R268.1 U24.6
SLIC_RST: U10.C12
SPDIF_OUT_BOOT_SEL1: R91.1 U9.1(TP-1) U10.B22
SPI_CSN0: U10.B13
SPI_CSN1: U10.A14
SPI_SDI: U10.D13
SPI_SDO: U10.C13
SPI_SLCK: U10.A13
STANDBY_PWROFF: R30.1 R33.1 R73.1 R88.1 R142.1 R163.1 U10.AG27
TSI0_CLK: J7.19 U10.N27
TSI0_D0: J7.17 U10.N28
TSI0_VALID: J7.21 U10.M26
TSI1_CLK: R10.1 U10.K28
TSI1_D0: R13.1 U10.L27
TSI1_SYNC: R226.1 U10.H26
TSI1_VALID: R5.1 U10.J27
TX+_PHY0: R80.1 U10.D5 U27.1 U27.8
TX-_PHY0: R79.1 U10.C5 U27.2 U27.7
UART0_RXD: J18.2 R136.1 U10.AF28
UART0_TXD: J18.3 R135.2 U10.AF27
USB0_DM: C341.2 D5.1 J6.2 U10.A8
USB0_DP: C342.2 D4.1 J6.3 U10.B8
USB01_1V1: C334.1 C336.1 LB31.2 U10.H11
USB01_3V3: C10.1 C182.1 LB20.2 U10.E10
USB1_DM: C343.2 D10.1 J9.2 U10.C9
USB1_DP: C344.2 D15.1 J9.3 U10.D9
USB01_VBUS: C49.1 C165.1 C353.1 C354.1 J6.1 J9.1 U26.5
USB2_DM: U7.4 U10.T27
USB2_DP: U7.3 U10.T28
USB2_RBI: R43.1 R85.1 U10.R25
USB3_DM: J12.2 U10.AH19
USB3_DP: J12.3 U10.AG19
USB3_REXT: R55.1 U10.AD18
USB3_RXN: J12.5 U10.AG21
USB3_RXP: J12.6 U10.AH21
USB3_TXN: C129.2 U10.AE20
USB3_TXP: C70.2 U10.AF20
USB_BOOT: R40.2 U10.A27
USBRBIAS: R44.2 R87.2 U10.G11
VDAC_3V3: C9.1 C85.1 LB14.2 U10.F23 U10.F24
VDAC_IREF: R32.2 U10.B24
WPS: U7.6
XIN: C364.1 R1.2 U10.AD27 X2.1
XOUT: R1.1 R14.1 U10.AD28
$4N758: D6.1 J10.2 LB6.1
$4N759: J10.1 J10.3 LB9.1
$4N770: C43.1 C71.1 R7.2 R21.1
$4N771: C76.1 R53.1 R70.1 R99.2 U11.6
$4N773: L4.1 U11.3
$4N777: R7.1 R70.2
$4N778: C8.1 R73.2 U11.1
$4N808: C45.1 C72.1 R23.1 R49.2
$4N809: R17.2 R49.1
$4N810: L3.1 U13.3
$4N813: C5.1 R142.2 U13.1
$4N877: C84.1 R52.1 R120.1 U15.5
$4N878: L2.1 U15.3
$4N879: C30.1 R6.2 R163.2 U15.1
$4N1045: R95.2 U18.5
$4N1055: C178.2 L8.1 U18.2
$4N1066: R190.1 U18.6
$4N1068: C178.1 R190.2
$4N1073: R172.1 U18.4
$4N1075: R105.1 R172.2 R191.1
$4N1115: L5.1 U1.3
$4N1116: C112.1 R100.1 R131.1 U1.5
$4N1127: C24.1 R48.2 U1.1
$4N1138: C82.1 R17.1 R47.1 R101.1 U13.6
$5N541: Q4.3 R118.2 R144.2
$5N542: C6.2 Q8.1 Q13.1 R118.1
$5N591: C133.2 Q3.1 R75.1
$5N592: Q9.3 R75.2 R98.2
$5N601: Q4.1 R33.2
$5N603: Q9.1 R30.2
$6N188: C365.1 R14.2 X2.3
$6N2484: R16.2 U10.E1
$7N2063: C146.1 R40.1 S10.1 S10.2
$8N1731: R45.1 U10.AC17
$8N1816: R36.2 U10.AF8
$8N1817: R37.2 U10.AG8
$11N894: R46.2 U3.L8
$12N1176: R71.2 U6.L8
$13N604: C123.1 C124.1 U22.K2
$13N821: R25.2 U19.38(TP-38)
$14N447: R220.1 U26.3
$14N448: R106.2 U26.4
$14N520: R113.1 U16.3
$14N521: R115.2 U16.4
$14N652: C70.1 J12.9
$14N653: C129.1 J12.8
$14N657: C52.1 C66.1 J12.1 U16.5
$15N771: C177.1 C181.1 D3.3 R178.2
$15N777: C157.2 Q15.1 R77.2 R175.1
$15N781: Q5.1 R76.2
$15N783: Q5.3 R175.2
$15N894: LED1.1 Q2.3 R34.2
$15N896: LED1.3 Q7.3 R129.2
$15N901: Q7.1 R22.2
$15N1018: Q2.1 R31.2
$16N873: C363.1 R90.2 R139.1 R229.1 U5.5
$16N884: C32.1 U5.7
$16N889: C33.2 U5.6
$16N895: C32.2 U5.8
$16N1022: C351.2 R193.1
$16N1024: C317.1 R19.1 R27.1 R193.2
$16N1034: C55.2 R19.2 R74.2 R146.1 U5.3
$16N1035: C55.1 R27.2 U5.2
$16N1048: C54.1 R97.1 R119.1 R145.1 U5.12
$16N1049: C350.1 R194.2
$16N1050: C316.1 R28.2 R97.2 R194.1
$16N1054: C54.2 R28.1 U5.13
$16N1079: R93.1 U5.11
$16N1086: R93.2 R94.1 R174.2
$17N163: C154.1 C297.1 T2.7(TP-7)
$17N165: J25.9 R67.1
$17N170: J25.11 R185.1
$17N171: J25.7 J25.8 R182.2
$17N172: R181.2 T2.15(TP-15)
$17N173: R180.2 T2.10(TP-10)
$17N175: J25.6 T2.9(TP-9)
$17N176: J25.3 T2.11(TP-11)
$17N177: C23.1 R180.1 R181.1 R182.1 R272.1
$17N178: J25.1 T2.16(TP-16)
$17N179: J25.2 T2.14(TP-14)
$17N180: J25.4 J25.5 R272.2
$17N184: C147.1 C153.1 T2.2(TP-2)
$17N276: R80.2 T2.1(TP-1)
$17N279: R79.2 T2.3(TP-3)
$17N281: R50.2 T2.6(TP-6)
$17N285: R18.2 T2.8(TP-8)
$19N506: D12.1 R184.1
$20N275: R69.2 R127.1 U2.37
$20N304: C226.1 U2.24
$20N444: C103.1 C204.1 LB10.1 LB13.1 LB15.1 R68.2 U12.2 U12.4
$20N446: R68.1 R141.1 U12.1
$21N322: C487.2 U34.26 U34.27
$21N324: C168.2 U34.24
$21N325: C190.1 C194.1 U34.20 U34.21 U34.22
$21N326: C538.1 R61.1 U34.15
$21N327: C534.1 R62.1 U34.16
$21N328: R72.1 U34.17
$21N329: C532.1 U34.18 X4.1
$21N330: C531.1 U34.19 X4.2
$21N331: R59.1 U34.14
$21N332: R64.1 U34.13
$21N333: C303.1 C537.1 U34.12
$21N334: C241.1 C307.1 U34.11
$21N336: C186.1 C535.1 U34.9
$21N337: C306.1 C536.1 U34.8
$21N338: L1.2 R63.1 U34.3
$21N360: C304.2 R63.2
$21N368: C64.2 C305.2 L1.1
$21N406: C148.1 U34.4
$21N416: C545.1 R60.2 U34.6
$21N439: R2.1 R112.1 U14.1(TP-1)
$21N597: C282.1 C283.2 L16.2
$21N600: C282.2 U34.7
$21N629: C105.1 C145.1 LB47.2 U14.3(TP-3)
$21N809: C171.2 U17.2
$21N822: C163.2 C175.2 U17.4
$21N827: C175.1 R102.2
$21N836: R117.2 U17.6
$21N838: R121.2 U17.7
$21N844: D7.1 L7.2 U17.15
$21N849: C139.1 U17.14
$21N851: C1.1 C139.2 D8.2 L9.2 U17.13
$21N859: C134.1 D7.2 L9.1
$21N880: C151.1 C167.1 C244.1 D8.1 D11.2 D17.1 U17.12
$21N898: R92.1 U17.11
$21N900: C246.1 U17.10
$21N922: Q6.1 R51.2 R114.1
$21N925: C155.1 R35.2 R114.2
$22N979: C490.1 J1.6 R39.2 R125.1 R126.2
$22N990: LB33.2 Q1.2 R20.1
$22N994: Q1.3 R302.1
$22N995: Q1.1 R20.2 R242.2
$22N1000: R168.2 U24.9
$22N1006: R270.1 U24.11 U24.13
$22N1011: Q14.2 R38.2 R267.2

Pads without a net: D6 3; ID1 1; ID2 1; ID3 1; ID4 1; ID5 1; ID6 1; J7 9 11 12 13 14 15 16 22; J26 14; J34 1 6; T2 4 5 12 13; U2 1 2 3 5 6 8 9 10 16 20; U3 J1 J9 L1 L9; U6 J1 J9 L1 L9; U10 AG9 AH9; U11 5; U13 5; U19 3 4 5 6 10 11 14 15 20 21 22 26 27 28 33 35 39 40 45 46 47; U22 1 2 A4 A6 A9 A11 AA1 AA2 AA7 AA8 AA9 AA10 AA11 AA12 AA13 AA14 AE1 AE14 AG2 AG13 AH4 AH6 AH9 AH11 B2 B13 D1 D14 H1 H2 H6 H7 H8 H9 H10 H11 H12 H13 H14 J1 J7 J8 J9 J10 J11 J12 J13 J14 K1 K3 K5 K7 K8 K9 K10 K11 K12 K13 K14 L1 L2 L3 L4 L12 L13 L14 M1 M2 M3 M5 M8 M9 M10 M12 M13 M14 N1 N2 N3 N10 N12 N13 N14 P1 P2 P3 P10 P12 P13 P14 R1 R2 R3 R5 R12 R13 R14 T1 T2 T3 T5 T12 T13 T14 U1 U2 U3 U6 U7 U10 U12 U13 U14 V1 V2 V3 V12 V13 V14 W1 W2 W3 W7 W8 W9 W10 W11 W12 W13 W14 Y1 Y3 Y6 Y7 Y8 Y9 Y10 Y11 Y12 Y13 Y14

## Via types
v1: diameter 0.559, hole 0.254, TOP to BOTTOM, 1859 vias
v2: diameter 0.457, hole 0.203, TOP to BOTTOM, 584 vias

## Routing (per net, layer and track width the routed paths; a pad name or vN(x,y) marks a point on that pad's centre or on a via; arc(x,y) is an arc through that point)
1V1_CORE: length 30.8
  TOP w0.254: U10.U14 v2(61.18,50.74) ; U10.K17 v2(64.38,57.14) ; U10.V16 v2(63.58,49.94) ; U10.T14 61.58,51.94 v2(61.18,52.34) U10.R14 ; U10.V13 60.38,49.94 ; U10.K16 v2(63.58,57.14) ; U10.M14 v2(61.18,55.54) ; U10.V14 v2(61.18,49.94) ; U10.R15 v2(62.78,52.34) ; U10.M15 v2(62.78,55.54) ; U10.T15 v2(62.78,51.54) ; U10.P15 v2(62.78,53.94) ; U10.K14 v2(61.18,57.14) ; U10.K15 v2(62.78,57.14) ; U10.T11 v2(58.78,51.54) ; U10.N15 v2(62.78,54.74) ; U10.V11 58.78,49.94 ; U10.P14 v2(61.18,53.94) U10.N14 ; U10.V12 v2(59.58,49.94) ; U10.U12 v2(59.58,50.74) ; U10.V15 v2(62.78,49.94) ; U10.U11 v2(58.78,50.74) ; U10.U13 v2(60.38,50.74) ; U10.U15 v2(62.78,50.74) ; U10.L15 v2(62.78,56.34) ; U10.R11 v2(58.78,52.34) ; U10.L14 v2(61.18,56.34)
  TOP w0.508: v1(69.5,21.34) R101.2 C82.2
  BOTTOM w0.381: C51.1 67.18,30.18 v1(66.65,30.71)
  BOTTOM w0.508: 68.45,30.43 68.45,26.57 69.11,25.91 70.48,25.91 70.99,25.4 70.99,22.82 v1(69.5,21.34)
  vias: v1(65.8,30.71) v1(66.65,31.55) v1(67.54,31.55) v1(67.54,30.71) v1(67.56,32.51)
1V1_CPU: length 19.9
  TOP w0.254: U10.N18 v2(65.18,54.74) ; U10.N22 v2(68.38,54.74) ; U10.P22 v2(68.38,53.94) ; U10.L21 v2(67.58,56.34) ; U10.M22 v2(68.38,55.54) ; U10.N19 v2(65.98,54.74) ; U10.P19 v2(65.98,53.94) ; U10.M21 v2(67.58,55.54) ; U10.R21 v2(67.58,52.34) ; U10.P18 v2(65.18,53.94)
  TOP w0.381: C35.1 88.58,54.04 88.77,53.85 90.43,53.85 92.21,52.07 98.68,52.07 99.47,52.86 C76.2 R53.2
  vias: v1(77.27,59.26) v1(77.27,57.99) v1(77.27,56.85) v1(78.16,59.26) v1(78.16,57.99) v1(78.16,56.85) v1(87.44,58.48) v1(87.5,57.66) v2(66.78,55.54)
1V2_ADC_S: length 5.8
  TOP w0.203: U2.33 86.87,71.02 86.87,71.81 v1(86.84,71.83)
  BOTTOM w0.508: LB13.2 86.26,73.62 C209.1 87.46,73.52 C125.1 87.5,72.39 86.94,71.83 v1(86.84,71.83)
1V2_APLL_S: length 5.4
  TOP w0.203: U2.28 88.88,71.41 89.28,71.81 v1(89.28,72.26)
  BOTTOM w0.508: v1(89.28,72.26) 89.38,72.36 C126.1 89.38,74.21 C210.1 89.53,74.36 LB15.2
1V2_DVDD_S: length 26.3
  TOP w0.203: v1(90.95,71.3) 90.65,71 U2.25 ; C110.1 92.27,67.52 U2.17 ; U2.42 v1(84.17,68.32) ; 88.08,64.62 U2.7
  TOP w0.381: v1(88.11,63.07) C113.1 88.11,64.59 88.08,64.62 ; C110.1 92.25,66.93 v1(91.69,66.93)
  BOTTOM w0.508: C117.1 87.53,63.73 87.12,64.14 87.12,65.02 85.6,66.55 C109.1 84.27,68.22 v1(84.17,68.32) ; C117.1 89.64,63.73 91.69,65.79 v1(91.69,66.93) 90.68,67.94 90.68,71.03 v1(90.95,71.3) v1(91.57,71.92) ; C117.1 88.14,63.09 v1(88.11,63.07)
1V5_DDR3: length 92.8
  TOP w0.254: U10.W9 v2(57.18,49.14) ; U10.T7 v2(55.58,51.54) 55.98,51.14 U10.U7 ; U3.K2 v2(37.39,60.64) ; U10.Y9 v2(57.18,48.34) ; U10.AB9 v2(57.18,46.74) ; U6.K2 v2(38.19,43.43) ; U10.AD4 v2(53.18,45.14) ; U10.R7 55.58,52.34 U10.R6 ; U10.AB12 v2(59.58,46.74) ; U10.AB10 v2(58.78,46.74) U10.AB11 ; U10.AC5 v2(53.98,45.94) ; U10.Y7 v2(55.58,48.34) ; U10.W7 55.98,49.54 v2(55.58,49.94) U10.V7 ; U10.Y11 v2(58.78,48.34) ; U10.AE6 55.18,44.74 v2(54.78,45.14) U10.AD6 ; U10.AB15 v2(62.78,46.74) ; U10.AE5 v2(53.98,44.34) ; U10.AA7 v2(55.58,47.54) ; U10.AB7 v2(55.58,46.74) ; U10.AC12 v2(59.58,45.94) ; U10.AB14 v2(61.18,46.74) U10.AB13 ; U10.N9 v2(57.18,54.74) ; U10.AC8 v2(56.38,45.94) ; U10.P7 v2(55.58,53.94) ; U3.N1 v2(34.99,60.64) ; U10.AD5 v2(53.98,45.14) ; U10.Y12 v2(59.58,48.34) ; U10.AB8 v2(56.38,46.74) ; U10.P9 v2(57.18,53.94) ; U10.AE4 v2(53.18,44.34) ; U10.AC6 v2(54.78,45.94) ; U10.N7 v2(55.58,54.74) ; U3.R1 v2(33.39,60.64) ; U10.AC7 v2(55.58,45.94) ; U10.AB6 v2(54.78,46.74)
  TOP w0.305: U6.E9 v2(41.79,37.68) ; U6.A8 v2(45.57,39.03) ; U6.C1 v2(43.39,45.17) ; v2(39.34,37.7) 39.38,37.7 39.39,37.71 U6.H9 ; U3.A8 v2(44.59,55.04) ; U6.R1 v2(33.79,45.18) ; v2(44.58,43.44) U6.B2 44.67,44.3 U6.A1 ; U6.D9 v2(42.59,37.68) ; U3.D2 v2(42.18,59.83) ; U3.B2 v2(44.6,60.64) U3.A1 ; U6.N1 v2(35.39,45.18) ; U6.H2 v2(39.78,44.21) ; U3.K8 v2(37.39,55.04) ; v2(43.52,61.59) 43.52,61.16 U3.C1 ; U6.C9 v2(43.39,37.68) ; U3.R9 v2(33.79,54.11) ; U3.H2 v2(38.98,59.83) ; U6.N9 v2(35.39,37.68) ; U3.C9 v2(43.79,54.24) ; U3.G7 v2(40.59,56.64) ; U3.F1 v2(40.99,61.61) ; U3.N9 v2(35.39,54.01) ; U6.R9 v2(33.79,37.68) ; U3.H9 v2(39.39,54.09) ; U6.K8 v2(37.38,38.62) ; U3.E9 v2(42.19,54.24) ; U6.D2 v2(42.98,43.44) ; U6.G7 v2(40.6,40.23) ; U3.D9 v2(42.99,54.24) ; U6.F1 v2(40.99,45.17)
  TOP w0.381: v2(29.49,42.15) 29.49,42.34 R26.2 ; v2(36.24,34.99) 36.66,34.57 R161.1 C222.1 ; v2(40.26,50.77) R158.1 C207.1
  TOP w0.508: C84.2 R120.2 32.44,69.32 v1(31.88,68.76)
  BOTTOM w0.381: C240.1 44.51,43.51 v2(44.58,43.44) ; C240.1 43.81,44.32 C228.1 43.59,44.98 v2(43.39,45.17) ; C240.1 43.05,43.51 v2(42.98,43.44) 42.34,42.8 42.32,42.8 41.57,42.05 41.54,42.05 C319.1 ; R54.1 v2(36.07,63.58) ; C211.1 41.91,53.96 v2(42.19,54.24) ; C213.1 43.51,60.66 43.31,60.45 C214.1 42.8,60.45 42.51,60.17 42.51,60.16 v2(42.18,59.83) 40.97,58.62 C315.1 ; C213.1 43.94,61.16 v2(43.52,61.59) ; C213.1 43.95,60.64 v2(44.6,60.64) ; v2(33.79,37.68) 33.79,37.09 C229.1 ; C233.1 38.19,42.84 v2(38.19,43.43) ; v2(40.6,40.23) 41.55,39.28 C106.1 ; C206.1 33.39,61.3 v2(33.39,60.64) ; C230.1 35.39,37.08 v2(35.39,37.68) ; v2(37.39,55.04) 37.47,55.11 C203.1 ; v2(40.99,61.61) 40.92,61.68 C219.1 ; C34.1 42.8,37.89 v2(42.59,37.68) ; C223.1 v2(41.03,48.44) ; C227.1 37.59,38.41 v2(37.38,38.62) ; v2(39.39,54.09) 39.39,53.65 C212.1 ; R78.1 v2(41.03,49.45) ; C215.1 45.62,38.97 v2(45.57,39.03) ; v2(33.79,54.11) 33.82,54.08 C237.1 ; C216.1 39.74,59.83 v2(38.98,59.83) ; C238.1 45.12,55.04 v2(44.59,55.04) v2(43.79,54.24) 43.94,54.08 C239.1 ; v1(43.69,68.63) 43.61,68.71 C68.1 ; v2(39.34,37.7) 39.73,38.09 C218.1 ; v2(39.78,44.21) 39.5,44.49 C232.1 ; C258.1 33.79,45.79 v2(33.79,45.18) ; v2(37.39,60.64) 36.98,60.23 C220.1 ; C208.1 v2(37.08,63.6)
  BOTTOM w0.508: v1(43.61,69.85) 35.18,69.85 34.09,68.76 v1(31.88,68.76)
  vias: v1(44.7,69.85) v1(44.7,68.63) v2(39.83,42.02) v2(39.83,41.31) v2(40.46,57.57) v2(41.35,57.57)
3V3: length 60.1
  TOP w0.254: R147.1 90.53,16.87 90.81,17.14 90.81,17.4 91.08,17.68 R122.1 v1(91.57,18.54)
  TOP w0.381: R136.2 v1(67.94,15.37) ; R34.1 R129.1 v1(86.56,18.57) ; v1(63.88,14.61) R100.2 C112.2 ; U10.AD23 v2(69.18,45.14) ; R41.1 v1(95.36,17.91) ; U10.AD24 v2(69.98,45.14)
  TOP w0.508: R178.1 78.23,14.76 v1(78.49,15.01) ; J18.4 64.45,12.84 66.12,14.5 R135.1 v1(66.67,15.37) ; R140.2 v1(72.49,15.67)
  BOTTOM w0.381: C13.1 68.96,41.83 ; C108.1 68.96,42.85 ; R88.2 69.98,41.83 ; R42.2 69.98,42.85
  BOTTOM w0.508: 58.72,22.63 58.72,22.17 62.48,18.41 62.48,16 v1(63.88,14.61)
  BOTTOM w0.762: v1(67.94,15.37) 68.25,15.67 v1(72.49,15.67) 73.33,16.51 75.69,16.51 77.19,15.01 v1(78.49,15.01) 80.67,15.01 84.23,18.57 v1(86.56,18.57) 91.54,18.57 v1(91.57,18.54) 94.73,18.54 v1(95.36,17.91)
  vias: v1(57.01,24.29) v1(57.01,23.37) v1(57.78,24.28) v1(57.78,23.37) v1(58.55,24.28) v1(58.55,23.37)
3V3_AVDD_S: length 10.6
  TOP w0.203: U2.30 88.08,71.83 v1(88.16,71.91)
  TOP w0.381: v1(81.41,72.64) 81.86,72.19 R69.1
  BOTTOM w0.508: v1(88.16,71.91) 87.19,70.94 C86.1 86.06,70.94 85.39,70.28 C201.1 84.77,70.42 83.57,71.63 LB5.2 81.75,72.3 v1(81.41,72.64)
3V3_DVDD_S: length 24.8
  TOP w0.203: v1(92.18,68.53) 91.9,68.25 91.31,68.25 91.24,68.32 U2.19 ; U2.4 86.88,64.58 ; 89.68,64.59 U2.11 ; U2.45 84.34,67.12 v1(84.2,66.98)
  TOP w0.381: v1(87.02,63.07) C75.1 87.02,64.45 86.88,64.58 ; R103.2 v1(78.41,71.17) ; 89.68,64.59 89.68,64.5 90.02,64.17 C74.1 v1(90.02,63.07)
  BOTTOM w0.381: C81.1 83.44,66.6 ; v1(78.41,71.17) 77.85,70.61 77.85,67.94 78.56,67.23 79.72,67.23 LB4.2 ; v1(90.02,63.07) 92.51,65.56 92.51,67.13 91.9,67.74 91.9,68.25 v1(92.18,68.53) ; C73.1 86.23,63.04
3V3_MOS: length 133.8
  TOP w0.254: U10.K24 v2(69.98,57.14) ; U10.E19 v2(65.98,61.14) ; U10.G5 v2(53.98,59.54) ; v1(78.74,69.22) 78.77,69.24 R104.1 ; R108.1 v1(78.74,67.94) ; U10.H24 v2(69.98,58.74) ; R96.2 v1(75.95,65.18) ; R91.2 v1(86.36,95.5) ; R125.2 v1(116.33,16.89) ; U10.E14 v2(61.18,61.14) ; U10.E13 v2(60.38,61.14)
  TOP w0.381: v1(88.84,75.11) 88.9,75.05 R65.1 ; R218.1 42.74,86.04 v1(43.05,85.72) ; v1(20.7,16.23) 20.95,16.48 R77.1 ; R155.1 v1(16.61,31.27) ; C157.1 v1(20.75,19.84) ; D9.2 75.95,96.27 75.75,96.46 v1(75.89,96.46) ; R66.1 90.2,75.08 v1(90.2,75.09) ; R219.1 v1(26,85.69)
  TOP w0.406: J25.12 41.96,96.45 41.96,89.84 41.52,89.4 41.52,86.29 41.77,86.04 R218.1 ; R219.1 26.38,86.47 26.76,86.85 26.76,89.75 26.13,90.39 26.13,97.01 27.69,98.57 J25.10
  TOP w0.508: R35.1 R116.2 125.07,83.95 v1(125.98,83.95) ; Q15.2 v1(23.72,23.27) ; D12.2 57.47,88.85 v1(57.47,88.62)
  POWER03 w0.635: J7.5 130.42,63.12 ; J7.5 128.19,63.12 ; J7.5 129.3,62 ; J7.5 129.3,64.24
  BOTTOM w0.254: Q14.1 v1(125.86,25.83) 125.63,25.6 R267.1
  BOTTOM w0.381: C15.1 54.03,59.59 v2(53.98,59.54) ; v2(58.72,60.3) 58.18,60.3 58.1,60.38 LB8.2 ; C198.1 69.35,57.76 v2(69.98,57.14) ; C199.1 69.96,58.72 v2(69.98,58.74) ; v2(61.18,61.14) 61.2,61.11 C245.1 ; v2(60.38,61.14) 60.58,61.34 LB20.1 ; R271.1 125.86,22.86 v1(125.22,23.49) ; LB7.2 v2(57.91,55.8)
  BOTTOM w0.508: LB14.1 74.68,60.71 v1(75.18,61.21)
  BOTTOM w0.762: v1(86.36,95.5) 85.4,96.46 v1(75.89,96.46) 75.2,97.16 59.69,97.16 57.47,94.94 v1(57.47,88.62) 57.47,87.56 55.64,85.72 v1(43.05,85.72) 26.04,85.72 v1(26,85.69)
  vias: v1(45.72,15.37) v1(46.74,15.37) v1(48.01,15.37) v1(49.15,15.37) v1(50.16,15.37) v1(73.41,75.56) v1(75.31,75.44) v1(79.12,70.48) v1(80.14,70.48) v1(107.44,46.23) v1(107.44,45.34) v1(119.15,65.41) v1(119.15,64.57) v1(124.46,36.96) v1(125.73,36.96) v1(126.11,83.06) v1(127,36.96) v1(127.13,83.95) v1(127.13,83.06) v1(128.27,36.96) v2(69.98,48.34) v2(69.98,47.54)
3V3_MOS_FLASH: length 43.9
  TOP w0.203: U22.Y4 U22.AA3
  TOP w0.254: v1(112.65,28.19) 112.16,27.7 U19.1 ; v1(105.16,30.66) 104.61,31.2 U22.AA3 ; U19.37 89.66,33.2 ; U22.N5 100.6,32.68 100.62,32.7 ; U22.K6 99.23,32.7 v2(99.59,33.06) 99.59,34.87 99.95,35.23 101.73,35.23 102.1,34.86 U22.T10 102.1,34.19 v2(102.08,34.18) 102.57,34.18 U22.U9 ; v2(103.07,31.7) U22.W4 U22.Y4 ; 112.26,33.2 U19.12 ; 100.62,32.7 v1(100.67,32.75) ; 100.62,32.7 U22.M6 ; U19.34 90.3,34.7 ; 112.23,39.2 U19.24 ; U22.AA5 v1(105.16,32.2)
  TOP w0.381: R212.1 v1(115.19,31.67) ; 88.7,33.45 88.95,33.2 89.66,33.2 ; 88.7,33.45 C22.1 ; 88.7,33.45 88.82,33.45 v1(89.28,33.91) 88.72,34.47 88.7,34.47 ; R176.1 v1(87,31.42) ; 90.3,34.7 88.93,34.7 88.7,34.47 ; R177.1 v1(87,30.4) ; R25.1 v1(87,32.44) ; 88.7,34.47 C323.1 ; R58.1 v1(87.12,35.48) ; R12.1 R189.1 v1(87.12,38.53) ; v1(113.64,39.65) C324.1 113,38.91 112.72,39.2 112.23,39.2 ; R188.1 v1(87,29.39) ; v1(113.64,33.86) C36.1 112.27,33.2 112.26,33.2 ; R203.1 v1(114.45,28.98) ; R29.1 v1(87.07,36.5) ; v1(105.16,30.66) 105.95,30.66 106.43,31.14 106.43,31.7 105.92,32.2 v1(105.16,32.2) ; R215.1 v1(114.45,37.19) ; R202.1 v1(87,28.37)
  BOTTOM w0.305: v2(102.08,34.18) 102.13,34.23 C143.1
  BOTTOM w0.381: v1(105.16,32.2) 104.44,32.2 C47.1 ; C93.1 98.84,33.06 v2(99.59,33.06) ; v2(103.07,31.7) 102.97,31.8 102.13,31.8 C142.1 ; v1(105.16,30.66) 105.03,30.53 C48.1
  vias: v1(117.98,32.64) v1(117.98,31.37) v1(119.13,32.64) v1(119.13,31.37)
3V3_RF: length 30.1
  TOP w0.203: U34.23 111.75,92.11 112.05,91.81 112.05,90.11 ; U34.28 111.26,94.11 111.86,94.11
  TOP w0.254: 111.86,94.11 112.11,94.11 113.06,95.06 C169.2
  TOP w0.381: C169.2 113.13,94.44 113.32,94.25 115.37,94.25 ; 112.05,90.11 112.68,89.47 C195.2 113.04,89.12 113.44,88.71 115.6,88.71 115.73,88.58
  TOP w0.508: 115.37,94.25 115.93,93.69 115.93,88.79 115.73,88.58
  TOP w0.635: 115.73,88.58 v1(115.76,88.55)
  BOTTOM w0.508: v1(125.53,89.92) 123.19,89.92 122.43,89.15 116.37,89.15 v1(115.76,88.55) ; v1(133.73,93.22) 133.73,93.6 134.09,93.95 R112.2
3V3_SD: length 23.8
  TOP w0.508: J13.4 11.58,25.17 13.67,27.25 15.95,27.25 16.41,27.71 C61.1 17.35,27.23 17.58,27 19.2,27 C28.1 20.02,24.84 R210.1 20.07,23.95 20.17,23.85 Q15.3
3V3_WIFI: length 0.9
  TOP w0.508: C60.1 110.54,42.72
5V0: length 33.1
  TOP w0.127: 56.96,14.72 56.97,14.72
  TOP w0.381: R48.1 v1(63.88,17.65)
  TOP w0.508: v1(37.95,68.55) 37.97,68.58 R6.1 ; R191.2 v1(24.13,72.77)
  BOTTOM w0.508: v1(37.95,68.55) 37.06,68.55 36.07,67.56 30.61,67.56 29.46,66.42 v1(21.08,66.42) ; v1(54.1,19.56) 53.8,19.86 R144.1 ; v1(24.13,72.77) 25.65,71.25 30.23,71.25 32.26,73.28 v1(32.26,74.35) ; v1(49.92,19.18) 50.67,19.93 C6.1
  vias: v1(32.26,75.11) v1(33.15,75.11) v1(33.15,74.35) v1(34.04,75.11) v1(34.04,74.35) v1(49.91,18.34) v1(49.91,17.53) v1(50.8,20.7) v1(56.04,14.94) v1(56.8,14.94) v1(57.57,14.94) v1(57.94,15.67) v1(58.33,14.94) v1(65.02,22.1) v1(65.91,22.1) v1(66.8,22.99) v1(66.8,22.1) v1(67.69,22.1) v1(93.34,52.71) v1(94.49,53.59) v1(94.49,52.71) v1(95.63,53.59) v1(95.63,52.71)
5V0_MOS: length 130.6
  TOP w0.381: R113.2 21.58,46.41 20.57,47.41 ; v1(61.06,94.82) 61.06,95.79 59.63,97.21 D13.2 ; U24.14 v1(122.06,26.03)
  TOP w0.508: C56.1 20.07,49.38 v1(20.07,48.69) ; R220.2 12.14,81.48 12.45,81.79 15.88,81.79 ; LB33.1 v1(117.73,21.59)
  BOTTOM w0.508: v1(83.82,94.23) v1(82.55,94.23) 80.77,94.23 80.26,94.74 75.72,94.74 ; 75.72,94.74 75.72,93.37 76.66,92.43 v1(76.66,89.68) v1(76.66,88.92) ; 75.72,94.74 74.75,95.71 61.94,95.71 v1(61.06,94.82) 60.05,93.81 60.05,87.6 56.26,83.82 25.78,83.82 19.94,89.66 15.24,89.66 14.73,90.17 13.59,90.17 12.72,89.31 12.72,87.07 16.18,83.62 ; 109.22,24.13 111.76,21.59 v1(117.73,21.59) 118.11,21.97 118.11,25.58 119.61,27.08 C87.2 122.05,26.04 v1(122.06,26.03)
  vias: v1(16.64,81.41) v1(16.64,80.39) v1(17.91,81.41) v1(17.91,80.39) v1(20.07,47.93) v1(43.81,22.48) v1(43.81,21.34) v1(43.81,20.07) v1(44.7,22.48) v1(44.7,21.34)
5V0_MOS_HDMI: length 12.9
  TOP w0.254: 56.87,98.95 56.7,99.12 J26.18
  TOP w0.381: 56.87,98.95 56.87,98.58 v1(57.53,97.92) 58.26,97.19 R187.2 ; U4.5 v1(58.74,94.14) ; R186.2 v1(56.48,97.2)
  TOP w0.508: 59.63,95.07 59.63,94.68 59.08,94.14 v1(58.74,94.14) ; 59.63,95.07 59.63,95.56 58.75,96.44 R187.2 ; 59.63,95.07 D13.1
  BOTTOM w0.508: v1(57.53,97.92) 57.2,97.92 v1(56.48,97.2) ; C150.1 58.77,94.11 v1(58.74,94.14)
12V0_MOS: length 84.6
  TOP w0.356: U17.3 v1(114.96,60.95)
  TOP w0.381: R121.1 R117.1 v1(118.23,58.04)
  POWER03 w0.635: 129.3,56.92 J7.1 ; J7.1 130.42,58.04 ; J7.1 128.19,58.04
  BOTTOM w0.381: v1(114.96,60.95) 114.3,61.61 C136.1
  BOTTOM w1.016: v1(42.8,81.71) v1(43.81,81.71) 54.81,81.71 68.2,68.33 74.7,68.33 86.82,56.21 108.05,56.21 v1(108.23,56.39) v1(108.99,57.15)
  vias: v1(107.87,57.35) v1(125.73,56.9) v1(126.87,57.02)
12V0_PWR: length 18.2
  TOP w0.508: v1(47.47,77.74) 46.67,78.54 Q3.2 v1(45.09,78.54) ; R95.1 v1(27.69,69.65)
  BOTTOM w0.508: v1(47.47,77.74) 48.13,77.08 v1(48.13,73.71) 48.08,73.66 R98.1 ; 24.38,75.06 22.99,73.66 22.99,72.01 25.35,69.65 v1(27.69,69.65)
  vias: v1(25.65,76) v1(25.78,74.98)
AVDD11_PLL012: length 1.1
  TOP w0.254: U10.U18 v2(65.18,50.74) ; U10.U19 v2(65.98,50.74)
AVDD11_USB3: length 1.1
  TOP w0.254: U10.Y18 v2(65.18,48.34) ; U10.Y19 v2(65.98,48.34)
AVDD33_ADAC: length 3.7
  TOP w0.254: U10.E22 v2(67.58,60.34)
  BOTTOM w0.381: LB35.2 67.53,62.55 C188.1 67.58,62.5 v2(67.58,60.34)
AVDD33_PLL01: length 0.6
  TOP w0.254: v2(68.38,49.14) 67.98,48.74 U10.Y22
AVDD33_USB2: length 2.4
  TOP w0.254: U10.U24 v2(69.98,51.54)
  BOTTOM w0.381: LB17.2 C3.1 69.77,51.33 v2(69.98,51.54)
AVDD33_USB3: length 3.3
  TOP w0.254: U10.AD20 U10.AD21
  TOP w0.305: v2(67.58,45.94) 67.18,45.54 U10.AD21
  BOTTOM w0.508: LB18.2 68.3,47.28 C18.1 67.96,45.94 v2(67.58,45.94)
DVDD11_LDO1_OUT: length 1.4
  TOP w0.254: U10.AA21 v2(66.78,47.54)
  BOTTOM w0.254: v2(66.78,47.54) 67.21,47.1 C255.2
GND: length 2004.1
  TOP w0.089: v2(104,29.74) 104.34,30.09 104.34,30.45 U22.Y2 103.85,30.45 103.85,29.89 v2(104,29.74)
  TOP w0.127: 71.91,51.28 73.33,51.28 ; 68.35,42.37 68.35,42.06 68.55,41.87 ; 65.15,43.43 64.9,43.18 64.9,41.78 64.64,41.53
  TOP w0.203: U22.AA4 U22.Y5 U22.AA6 ; U6.J8 38.59,39.22 38.2,39.61 38.2,40.17 v2(38.3,40.27) ; U10.Y2 52.15,48.74 52.55,48.34 53.18,48.34 U10.Y4 ; U2.34 86.49,71.01 86.49,71.42 86.33,71.58 86.33,72.19 v1(86.72,72.57) ; U2.29 88.48,71.49 88.7,71.7 88.7,72.09 88.21,72.58 v1(88.21,72.72) 88.21,72.82 ; U10.AG5 54.38,43.38 54.78,43.78 v2(54.78,44.34) ; v2(56.38,44.34) 56.38,43.73 55.98,43.33 U10.AG7 ; U3.J8 38.98,55.83 38.98,56.53 ; v1(86.61,66.73) 86.21,66.32 U2.47
  TOP w0.229: U22.K4 99.58,32.19 99.58,32.28 99.58,32.28 v2(99.58,32.29)
  TOP w0.254: U10.G8 v2(56.38,59.54) ; U10.P17 v2(64.38,53.94) ; U10.AG1 v2(50.78,42.74) ; U10.P16 v2(63.58,53.94) ; U19.36 v1(92.71,33.7) ; U10.E8 v2(56.38,61.14) ; U10.L18 v2(65.18,56.34) ; U10.G24 v2(69.18,59.54) ; U10.J4 v2(53.18,57.94) ; U10.L12 v2(59.58,56.34) ; v1(111.51,46.61) 110.97,47.14 106.27,47.14 105.1,45.97 v1(104.14,45.97) v1(100.33,45.97) v1(96.39,45.97) 90.3,45.97 v1(87.63,48.64) 87.07,49.2 81.53,49.2 79.81,50.93 v1(77.98,50.93) 77.22,50.93 76.98,51.16 73.98,51.16 73.86,51.28 73.33,51.28 ; U10.B2 v2(51.58,63.54) ; U10.AH10 v2(58.38,41.71) ; U10.E26 71.58,61.14 ; R146.2 67.54,95.65 67.51,95.67 ; U10.V6 v2(54.78,49.94) ; U10.M17 v2(64.38,55.54) ; v1(80.41,30.2) v1(82.55,28.07) v1(85.09,25.53) 85.72,24.89 v1(88.9,24.89) v1(91.44,24.89) v1(93.98,24.89) v1(97.16,24.89) v1(100.33,24.89) v1(104.14,24.89) 106.68,24.89 v1(107.95,26.16) 108.7,26.91 113.86,26.91 114.38,27.43 v1(115.19,27.43) 120.02,27.43 v1(121.28,28.7) 121.59,29.01 v1(122.3,29.01) ; v2(50.65,58.36) 50.67,58.34 U10.H1 ; v1(73.86,48.82) 74.3,48.39 75.87,48.39 76.83,47.42 79.5,47.42 80.26,46.66 85.22,46.66 87.88,43.99 v1(87.88,43.31) 87.88,42.16 ; U10.A2 v2(51.58,64.34) U10.A1 ; U10.B26 v2(71.58,63.54) ; U10.Y27 v2(71.58,48.34) ; U10.L2 v2(51.58,56.34) ; 52.96,18.21 53.85,18.21 v1(54.23,18.59) ; v1(108.52,37.78) 105.41,40.89 v1(96.9,40.89) 95.76,40.89 v1(93.98,42.67) 93.34,43.31 v1(89.28,43.31) 89.28,43.87 85.72,47.42 80.59,47.42 79.83,48.18 77.09,48.18 76.2,49.07 75.06,49.07 v1(74.93,49.2) ; C221.2 v1(81.28,67.87) ; U10.D8 v2(56.38,61.94) U10.C8 ; U10.M16 v2(63.58,55.54) ; U10.P6 v2(54.78,53.94) ; v1(68.69,88.03) 68.69,88.79 69.32,89.41 69.32,93.37 v1(69.62,93.68) ; U10.G17 v2(64.38,59.54) ; 43.79,107.47 J26.23 45.45,105.66 ; U10.R16 v2(63.58,52.34) ; v1(44.83,63.37) 45.14,63.37 46.2,62.31 v2(46.2,62.23) 46.3,62.23 47.29,61.24 v1(47.29,60.93) 47.29,60.78 C118.1 47.4,60.04 47.4,59.77 v2(48.62,58.55) v2(49.23,57.94) 50.37,56.79 50.42,56.79 ; J26.21 45.45,103.87 ; J26.21 47.03,101.51 ; J26.21 45.45,99.3 ; J26.21 43.85,101.51 ; U10.W5 v2(53.98,49.14) U10.Y4 ; U10.L16 v2(63.58,56.34) ; U10.R24 v2(69.98,52.34) ; U10.AC13 v2(60.38,45.94) ; J26.20 59.95,103.91 ; J26.20 61.33,101.51 ; J26.20 59.95,99.32 ; U10.J22 68.38,57.94 ; v1(135.38,70.1) v1(135.38,64.67) v1(135.38,58.17) 135.38,56.39 v1(133.92,54.93) 131.95,52.96 v1(131.44,52.96) v1(127.51,52.96) v1(123.32,52.96) v1(119.76,52.96) 118.24,52.96 v1(116.84,54.36) 111.56,54.36 108.89,51.69 v1(107.19,51.69) 106.55,51.69 104.32,49.45 v1(102.41,49.45) v1(97.03,49.45) v1(93.22,49.45) 91.14,49.45 v1(90.49,50.1) 88.9,51.69 82.85,51.69 80.57,53.98 v1(79.38,53.98) 75.69,53.98 75.56,53.85 74.07,53.85 73.79,53.57 73.3,53.57 ; U3.J2 v2(38.99,60.64) ; v1(90.3,27.91) 90.5,27.7 U19.48 ; U10.D25 v2(70.78,61.94) ; U10.AG13 v2(60.38,42.74) U10.AH12 ; U22.AA6 104.92,32.7 v1(105.18,32.97) ; U10.P26 v2(71.58,53.94) ; U10.D7 v2(55.58,61.94) ; U10.AE25 v2(70.78,44.34) ; U10.AD14 61.58,45.54 v2(61.18,45.94) U10.AC14 ; U19.13 109.81,33.7 ; U10.L5 v2(53.98,56.34) ; U10.AD22 v2(68.38,45.14) ; v1(43.84,65.86) v1(40.06,65.86) v1(36.22,65.86) v1(33.25,65.86) v1(30.02,65.86) 25.86,65.86 v1(25.15,65.15) 23.75,63.75 v1(20.59,63.75) 17.6,63.75 14.99,61.14 v1(14.99,59.18) 14.99,56.82 v1(14.61,56.44) 13.78,56.44 13.13,57.09 13.13,57.63 v1(13.34,57.84) 13.84,58.34 13.84,61.14 17.48,64.77 v1(18.29,64.77) 23.24,64.77 v1(24,65.53) 25.32,66.85 v1(30.94,66.85) v1(34.52,66.85) v1(41.4,66.85) 46.56,66.85 v1(46.61,66.8) 46.86,66.8 48.26,65.41 48.26,63.88 50.9,61.24 51.47,61.24 v2(51.58,61.14) U10.E2 51.48,60.24 U10.F1 v2(50.62,59.94) 50.62,60.62 47.32,63.92 ; U10.T22 v2(68.38,51.54) ; U10.D24 v2(69.98,61.94) ; U10.C3 v2(52.38,62.74) ; U10.R26 v2(71.58,52.34) ; v2(69.98,59.54) U10.G25 ; U10.K25 v2(70.78,57.14) ; U10.J26 v2(71.58,57.94) ; U10.F4 v2(53.18,60.34) ; U3.P1 v2(34.19,60.64) ; U10.B27 v2(72.38,63.54) ; U10.J21 v2(67.58,57.94) ; U10.J3 v2(52.38,57.94) U10.H2 ; U10.R17 v2(64.38,52.34) ; U10.AF3 52.78,43.94 v2(52.38,44.34) U10.AE3 ; U10.L3 v2(52.38,56.34) U10.K3 ; U3.M1 v2(36.59,60.64) ; 59.95,104.96 J26.22 58.21,107.47 ; J18.1 69.27,10.97 ; J18.1 68.2,9.78 ; J18.1 68.2,12.19 ; U10.M12 v2(59.58,55.54) ; U10.K11 v2(58.78,57.14) ; U10.N11 v2(58.78,54.74) ; v2(53.45,41.83) 53.58,41.96 U10.AH4 ; U10.P12 v2(59.58,53.94) ; U10.P11 v2(58.78,53.94) ; U10.W24 69.58,49.54 v2(69.98,49.94) U10.V24 ; U10.AC10 v2(57.98,45.94) ; U10.R13 v2(60.38,52.34) ; U10.AG11 v2(59.58,43.54) ; U10.J25 v2(70.78,57.94) ; U10.N16 v2(63.58,54.74) ; U10.E5 v2(53.98,61.14) ; v1(105.77,31.36) 105.77,31.37 105.21,31.37 104.87,31.7 U22.AA4 ; U10.E20 v2(66.78,61.14) ; U10.K21 v2(67.58,57.14) ; U10.U16 63.58,50.74 ; U10.Y10 v2(57.98,48.34) ; U10.D10 v2(57.98,61.94) ; U10.T19 v2(65.98,51.54) ; 73.15,52.5 75.12,52.5 75.31,52.69 80.28,52.69 v1(81.53,51.44) 82.3,50.67 v2(86.36,50.67) 88.32,50.67 91.24,47.75 v1(91.95,47.75) v1(95,47.75) v1(99.57,47.75) 104.39,47.75 v1(105.09,48.45) 105.66,49.02 v1(111.25,49.02) ; U10.C19 v2(65.98,62.74) U10.C20 ; U10.AC24 v2(69.98,45.94) ; U10.AA6 v2(54.78,47.54) 54.38,47.14 U10.AB5 ; U10.U6 v2(54.78,50.74) ; U10.AD3 v2(52.38,45.14) ; U10.A3 v2(52.38,64.34) ; U10.E4 v2(53.18,61.14) ; v1(115.06,16.81) 115.06,17.02 115.95,17.91 v1(125.32,17.91) 126.44,17.91 129.68,21.14 U24.7 v1(129.68,23.92) 129.08,24.51 v1(123.7,24.51) 120.27,24.51 v1(119.38,25.4) 118.72,26.06 v1(115.95,26.06) 115.75,26.26 109.69,26.26 v1(109.15,25.72) 107.05,23.62 v1(106.05,23.62) v1(102.87,23.62) v1(99.06,23.62) v1(95.25,23.62) v1(92.71,23.62) v1(90.17,23.62) v1(87.63,23.62) 85.09,23.62 v1(83.19,25.53) v1(79.38,29.34) v1(76.2,32.51) v1(74.3,34.42) ; v1(78.87,65.84) 78.23,65.2 78.23,63.17 v1(75.76,60.69) 75.16,60.1 v1(75.16,58.62) 75.16,58.19 74.63,57.66 72.9,57.66 v2(72.38,57.14) U10.K27 ; C339.2 69.44,98.48 v1(69.42,98.5) ; U10.H25 v2(70.78,58.74) ; U3.T1 v2(32.59,60.64) ; U10.W1 50.67,49.54 v2(50.55,49.66) ; U10.R3 v2(52.38,52.34) ; U10.AE26 v2(71.58,44.34) ; 68.2,36.5 68.61,36.91 68.61,41.81 68.55,41.87 ; U19.23 112.1,38.7 v1(112.39,38.4) ; U10.AE7 v2(55.58,44.34) ; U10.F3 v2(52.38,60.34) ; v1(72.45,78.55) 72.39,78.49 v1(72.39,74.42) v1(72.39,71.88) v1(72.39,69.34) ; U10.Y13 v2(60.38,48.34) ; U10.K13 v2(60.38,57.14) ; U10.T13 v2(60.38,51.54) ; U10.M3 v2(52.38,55.54) ; U10.U17 v2(64.38,50.74) ; U10.T12 v2(59.58,51.54) ; U10.AF19 v2(65.98,43.54) ; U10.AE1 v2(50.78,44.34) ; v1(133.79,77.03) 134.37,76.45 v1(134.37,67.56) v1(134.37,63.27) 134.37,57.15 v1(133.41,56.2) 131.24,54.03 v1(129.03,54.03) v1(125.09,54.03) v1(121.16,54.03) 119.76,54.03 v1(118.49,55.3) v1(113.18,55.3) 111.43,55.3 108.84,52.71 v1(108.08,52.71) 106.05,52.71 v1(104.9,51.56) 103.81,50.47 v1(101.02,50.47) v1(96.27,50.47) 91.64,50.47 v1(90.55,51.56) 89.66,52.45 83.31,52.45 v1(82.42,53.34) 80.84,54.93 75.05,54.93 v1(74.89,54.76) ; U10.L19 v2(65.98,56.34) ; U10.T17 v2(64.38,51.54) ; U10.H4 v2(53.18,58.74) ; U10.E24 v2(69.98,61.14) ; U10.E11 v2(58.78,61.14) ; U10.V5 v2(53.98,49.94) ; U6.J2 v2(38.19,44.23) ; U10.L1 v2(50.78,56.34) ; U10.R9 v2(57.18,52.34) ; U10.D16 v2(63.58,61.94) ; U10.AC15 v2(62.78,45.94) U10.AD16 ; U10.M13 v2(60.38,55.54) ; v1(73.91,56.77) 74.75,56.77 76.15,58.17 v1(76.15,58.62) 76.15,59.72 v1(77.27,60.83) 78.97,62.53 v1(78.99,62.53) 78.99,63.88 79.38,64.26 83.31,64.26 v1(83.57,64.52) ; U10.R12 v2(59.58,52.34) ; U10.K22 v2(68.38,57.14) ; U10.AE10 v2(57.98,44.34) ; J26.5 v1(50.2,99.03) ; v2(54.78,61.94) U10.D6 v2(54.78,61.14) ; U10.N13 v2(60.38,54.74) ; U10.L17 v2(64.38,56.34) ; U10.V2 U10.V3 v2(53.18,50.74) ; U10.W6 54.78,49.14 ; U19.2 110.11,28.2 109.86,28.46 v1(109.86,29.34) 109.86,29.67 108.53,30.99 108.53,35.48 108.08,35.94 108.08,36.45 v1(106.68,37.85) 104.84,39.69 v1(94.81,39.69) ; U10.L22 v2(68.38,56.34) ; U10.P24 v2(69.98,53.94) ; U10.H5 v2(53.98,58.74) ; U10.AG2 v2(51.58,42.74) ; U10.T25 v2(70.78,51.54) ; J26.2 v1(48.7,99.03) ; U10.AC16 v2(63.58,45.94) U10.AD17 ; v1(76.2,34.42) v1(78.11,32.51) ; U10.AE23 v2(68.38,44.34) U10.AE22 U10.AE21 ; U10.T26 v2(71.58,51.54) ; U10.AC9 v2(57.18,45.94) ; U10.H22 68.38,58.74 ; U10.AC4 v2(53.18,45.94) ; U10.N25 v2(70.78,54.74) ; v2(53.98,53.14) 54.38,52.74 U10.R5 ; v2(61.18,44.34) 61.58,43.94 U10.AF14 ; U10.AB2 51.79,47.14 51.31,46.66 v2(50.8,46.66) ; U10.R18 v2(65.18,52.34) ; U10.AE18 v2(65.18,44.34) 64.78,43.94 U10.AF18 ; U10.E9 v2(57.18,61.14) ; 110.01,93.67 v1(110.04,93.67) ; U10.V9 v2(57.18,49.94) ; v2(72.36,47.52) U10.AB27 ; U24.2 v1(123.33,23.49) ; U10.T4 v2(53.98,51.54) ; U10.AE8 v2(56.38,44.34) ; U10.AF2 v2(51.58,43.54) ; U10.AF9 v2(57.18,43.54) ; U10.C6 v2(54.78,62.74) ; U10.G21 67.58,59.54 ; J26.11 v1(53.2,99.03) ; U10.N12 v2(59.58,54.74) ; U10.H12 v2(59.58,58.74) ; U10.H13 v2(60.38,58.74) ; U10.Y6 v2(54.78,48.34) ; U10.C4 v2(53.18,62.74) ; D3.2 74.52,11.4 ; D3.2 73.35,10.34 ; D3.2 74.52,8.99 ; D3.2 75.62,10.34 ; U10.U22 68.38,50.74 ; J26.8 v1(51.7,99.03) ; v2(68.38,61.94) U10.C22 68.4,62.76 v1(68.4,65.53) 68.4,66.67 68.45,66.73 68.45,66.84 68.86,67.25 v1(68.86,69.32) v1(68.86,71.6) v1(68.86,74.14) v1(68.86,76.05) ; U10.C18 v2(65.18,62.74) ; U10.C26 v2(71.58,62.74) ; U10.G4 v2(53.18,59.54) ; U10.L13 v2(60.38,56.34) ; U10.AA1 50.63,47.94 v2(50.55,47.86) ; U10.B25 v2(70.78,63.54) ; U10.D20 v2(65.98,61.94) U10.D19 ; U10.C16 v2(63.58,62.74) ; U10.H21 v2(67.58,58.74) ; U10.E15 v2(62.78,61.14) ; U10.E23 v2(69.18,61.14) ; U10.P25 v2(70.78,53.94) ; U10.M11 v2(58.78,55.54) ; U10.K18 65.18,57.14 ; U10.AH6 v2(55.18,41.71) ; U10.D22 v2(68.38,61.14) ; v2(68.38,43.54) U10.AF22 U10.AF21 ; U10.AB25 v2(70.78,46.74) ; U10.G26 v2(70.78,59.54) ; U10.K19 v2(65.98,57.14) ; U10.B14 v2(61.18,63.54) ; U10.E12 v2(59.58,61.14) ; U10.N17 v2(64.38,54.74) ; U10.M6 v2(54.78,55.54) ; v1(90.3,39.04) 90.46,39.2 U19.25 ; U10.Y15 v2(61.98,48.34) ; U10.AH27 v2(72.38,41.94) ; U10.L4 v2(53.18,56.34) ; 79.25,97.92 v1(79.25,95.63) v1(79.25,93.85) v1(79.25,91.31) 79.25,89.41 79.63,89.03 ; U10.D14 v2(61.18,61.94) ; U10.AF16 v2(63.58,43.54) ; U10.AD26 v2(71.58,45.14) ; U10.AF25 v2(70.78,43.54) ; U10.J24 v2(69.98,57.94) ; U10.A28 v2(72.78,64.52) ; U10.AH2 v2(51.58,41.94) ; C316.2 70.66,84.35 v1(70.92,84.61) 71.58,83.95 71.58,81.58 v1(71.04,81.05) v1(71.04,74.3) v1(71.04,71.75) v1(71.04,69.34) 71.04,66.22 v1(70.74,65.91) ; U10.T16 v2(63.58,51.54) ; U10.U9 57.18,50.74 ; U10.P2 v2(51.58,53.94) ; U10.C10 v2(57.98,62.74) ; U10.B3 v2(52.38,63.54) ; 66.06,64.79 66.06,77.3 65.79,77.57 ; U10.C7 v2(55.58,62.74) ; U10.C25 v2(70.78,62.74) ; C217.2 v1(81.28,69.22) ; U10.F5 v2(53.98,60.34) ; U10.T18 v2(65.18,51.54) ; U10.G19 v2(65.98,59.54) ; U10.J5 v2(53.98,57.94) ; U10.K26 v2(71.58,57.14) ; U10.C14 v2(61.18,62.74) ; U10.M4 v2(53.18,55.54) ; U10.AD9 v2(57.18,45.14) ; U10.N24 v2(69.98,54.74) ; U10.AF15 v2(62.78,43.54) ; U10.AE19 v2(65.98,44.34) ; U10.U21 67.58,50.74 ; J26.17 v1(56.2,99.03) ; U10.AC11 v2(58.78,45.94) ; U10.AH1 v2(50.78,41.94) ; U10.AD12 v2(59.58,45.14) ; U10.N3 v2(52.38,54.74) ; U10.AD25 v2(70.78,45.14) ; U10.AB16 v2(63.58,46.74) ; U10.B4 v2(53.18,63.54) ; U10.AA20 v2(65.98,47.54) ; U10.E25 70.78,61.14 ; U10.T6 v2(54.78,51.54) ; U10.P13 v2(60.38,53.94) ; U10.R22 v2(68.38,52.34) ; U10.V25 v2(70.78,49.94) ; U10.N26 v2(71.58,54.74) ; U10.C24 v2(69.98,62.74) ; U10.M5 v2(53.98,55.54) ; U10.D4 v2(53.18,61.94) ; U10.N6 v2(54.78,54.74) ; v2(69.98,49.14) U10.Y25 ; U10.R1 v2(50.55,52.74)
  TOP w0.305: U3.E1 41.79,61.05 v2(42.31,61.57) 42.59,61.29 U3.D1 ; U6.T9 v2(32.99,37.68) ; U3.B1 v2(44.6,61.44) ; U6.E2 v2(42.18,44.21) 41.79,44.6 U6.E1 ; U3.G1 v2(40.19,61.61) ; U3.D8 v2(42.99,55.04) ; v1(50.06,96.8) v1(50.06,95.33) v1(50.06,93.73) ; U6.M9 v2(36.19,37.68) ; U6.D8 v2(42.19,39.43) U6.E8 ; U3.G8 v2(40.59,55.84) ; v1(48.46,93.77) U23.3 U23.8 v1(48.46,96.8) ; v1(51.63,96.75) U8.8 U8.3 v1(51.63,93.77) ; U6.G9 40.19,37.7 40.21,37.68 v2(40.16,37.68) ; U6.A9 v2(44.99,37.68) ; U6.P9 v2(34.59,37.68) ; C79.2 77.3,94.78 v1(77.3,94.01) 77.3,93.36 R9.2 ; U6.P1 v2(34.59,45.18) ; U6.M1 v2(36.19,45.18) ; U6.G1 v2(40.19,45.59) ; U6.B3 v2(44.58,42.64) ; U3.A9 v2(44.59,54.24) ; U6.B9 44.19,37.79 v2(44.28,37.7) ; U6.D1 v2(42.59,45.17) ; U3.E2 v2(42.2,60.64) ; v2(40.99,37.68) 41.01,37.68 40.99,37.7 U6.F9 ; U3.G9 v2(40.19,54.09) ; U3.B3 v2(44.6,59.84) ; U3.P9 v2(34.19,55.04) ; 38.98,56.53 38.98,56.59 v2(39.39,57) ; U17.1 113.66,61.08 ; U6.T1 v2(32.6,45.02) ; U3.M9 v2(36.19,54.09) ; U3.B9 v2(43.79,55.04) ; U3.F9 v2(40.99,54.09) ; U3.E8 v2(42.19,55.04) ; U3.T9 v2(32.99,54.09) ; U6.G8 v2(40.6,39.43) ; U6.B1 v2(44.19,45.17)
  TOP w0.356: 67.51,95.67 v1(67.51,94.95) ; U5.10 v1(71.17,91.4) ; U5.1 v1(67.61,94) v1(68.63,95.01) R145.2 ; v1(69.62,93.68) 69.94,94 v1(71.17,94) U5.14 ; U5.4 67.47,92.05 v1(67.69,91.82)
  TOP w0.381: C36.2 v1(114.45,33.83) ; C74.2 v1(90.83,63.02) ; C538.2 v1(103.38,87.95) ; C490.2 v1(117.6,16.81) ; v1(58.83,92) R8.1 ; Q2.2 v1(81.66,14.35) ; D5.2 v1(11.96,67.51) ; C310.2 R107.2 40.47,34.57 v2(40.53,34.63) ; C324.2 v1(114.45,39.65) ; v1(98.77,95.25) 100.11,96.58 v1(100.11,96.71) ; C226.2 v1(93.37,71.27) ; R92.2 v1(118.07,72.05) ; C363.2 v1(62.28,91.41) ; C489.2 v1(115.06,16.81) ; 96.53,107.77 J16.4 ; J16.4 102.47,107.77 ; J16.4 99.5,106.45 ; J16.4 99.5,109.09 ; C181.2 75.45,15.36 v1(75.18,15.62) ; R131.2 v1(63.88,16.64) ; v2(35.78,51.09) 36.1,50.77 R159.2 C289.2 ; R57.2 v1(88.9,16.13) ; C110.2 C38.2 v1(94.23,66.22) ; v1(115.26,93.41) C487.1 ; R86.2 77.98,44.6 77.98,43.87 ; C149.2 v1(58.79,90.98) ; C22.2 v1(87.02,33.45) ; C8.2 v1(100.28,58.6) ; C537.2 v1(103.38,90.49) ; 79.25,97.92 v1(79.25,97.97) C17.2 ; R126.1 v1(118.87,16.81) ; R124.1 v1(110.69,15.04) ; v1(75.77,91.77) 76.02,92.02 R94.2 ; v1(14.05,89.36) 14.02,89.38 C343.1 D10.2 ; C113.2 v1(88.93,64.52) ; R82.1 48.01,68.96 v1(47.62,69.34) ; C317.2 v1(66.47,84.35) ; R83.2 v1(94.23,65.2) ; C176.2 v1(78.87,65.84) ; 92,102.15 J16.5 ; J16.5 93.32,104.23 ; J16.5 94.64,102.15 ; J16.5 93.32,100.07 ; C172.2 v1(95.4,70.05) ; v1(83.57,74.22) C37.2 ; v1(100.11,87.19) v1(101.12,88.2) ; v1(100.33,53.21) 100.56,53.44 C43.2 ; R99.1 v1(100.23,57.15) ; C30.2 v1(35.94,68.58) ; R3.2 v1(81.28,70.15) ; C169.1 v1(115.42,95.06) ; v1(103.41,95.7) 104.05,95.7 C545.2 ; C323.2 v1(87,34.47) ; C491.2 v1(111.89,16.81) ; R47.2 73,22.99 v1(73.13,23.11) ; R4.2 v1(94.23,64.19) ; R56.1 v1(79.25,49.07) ; C159.2 v1(85.09,95.38) ; 92,83.65 J16.6 93.32,85.73 ; J13.6 v1(3.3,27.36) ; R64.2 v1(101.12,89.22) ; D4.2 v1(11.96,64.92) ; C39.2 v1(110.67,16.31) ; v1(103.41,94.68) 104.05,94.68 C536.2 ; C115.2 v1(115.19,30.66) ; U4.2 v1(53.76,94.14) ; R59.2 v1(103.35,89.22) ; v1(96.23,92.71) v1(94.77,91.25) ; v1(104.02,92.65) C535.2 ; v1(104.02,92.65) C241.2 ; v1(104.02,92.65) v1(100.98,92.65) ; C534.2 v1(103.35,86.68) ; C75.2 v1(85.47,63.8) ; C45.2 v1(73.15,25.91) ; C246.2 v1(119.34,72.77) ; v1(114.45,35.86) R89.2 ; v1(95.25,67.34) C174.2
  TOP w0.457: 88.21,72.82 88.21,74.13 88.1,74.24 88.1,75.53 90.81,78.23 v1(91.31,78.23) v1(95.25,78.23) v1(96.33,79.31) v1(97.47,80.45) v1(98.97,81.95) v1(98.97,83.63) v1(98.97,84.9) v1(98.97,86.17) v1(98.97,87.44) v1(98.97,88.71) 98.97,88.84 v1(99.85,89.73) 100.62,90.49 v1(101.12,90.49) ; v1(98.84,91.38) v1(97.44,89.98) v1(97.44,88.71) v1(97.44,87.44) v1(97.44,86.17) v1(97.44,84.9) v1(97.44,83.63) v1(97.44,82.46) v1(96.27,81.28) v1(95.19,80.2) 94.74,79.76 v1(93.34,79.76) v1(91.57,79.76) v1(89.92,79.76) v1(89.15,78.99) 86.72,76.56 v1(86.72,75.95) v1(86.72,72.57) ; v1(90.5,72.37) 91.03,72.9 v1(91.03,75.11) 91.03,75.67 v1(91.31,75.95) v1(91.92,76.56) 92.33,76.96 95.89,76.96 v1(96.46,77.53) v1(97.41,78.49) v1(98.11,79.18) v1(99,80.07) v1(99.76,80.84) 100.4,81.47 ; v1(94.77,91.25) v1(94.77,89.98) v1(94.77,88.71) v1(94.77,87.44) v1(94.77,86.17) v1(94.77,84.9) v1(94.77,83.63) ; v1(85.09,71.3) v1(85.09,72.64) v1(85.09,76.71) 85.09,77.22 v1(86.87,78.99) v1(87.63,79.76) v1(88.58,80.71) 89.15,81.28 v1(89.53,81.28) v1(91.82,81.28) v1(94.11,81.28) v1(94.93,82.11) 95.87,83.04 v1(95.87,83.63) v1(95.87,84.9) v1(95.87,86.17) v1(95.87,87.44) v1(95.87,88.71) v1(95.87,89.98) 95.87,90.69 v1(97.06,91.89) v1(98.01,92.84) v1(99.28,94.11) 100.24,95.06 v1(101,95.06)
  TOP w0.508: v1(69.34,26.8) 69.19,26.64 U13.2 ; v1(53.47,92.58) 53.47,88.9 ; 53.47,88.9 v1(53.46,88.91) ; 53.47,88.9 v1(54.36,88.01) v1(55.37,86.99) 56.72,85.65 57.68,85.65 v1(59.23,84.1) 59.26,84.1 v1(61.35,82) v1(63.47,79.88) 65.79,77.57 v1(65.79,77.6) ; Q6.2 v1(125.09,78.87) ; 8.03,52.76 J12.10 5.96,50.68 ; J12.11 5.38,37.54 ; J12.11 8.03,35.4 ; J12.11 10.08,37.54 ; C60.2 v1(108,42.72) ; C205.2 v1(92.2,75.06) ; LED1.2 82.5,8.03 ; v1(60.2,19.43) 59.94,19.18 U1.2 ; C140.2 65.89,97.68 v1(65.41,98.17) ; D9.1 v1(74.8,94.49) ; 55.32,23.62 v1(57.19,25.49) v1(59.73,28.03) v1(62.27,30.57) v1(64.81,33.11) v1(67.35,35.65) 68.2,36.5 ; C177.2 v1(73.94,14.76) ; 56.39,74.93 J3.1 58.17,73.41 ; C202.2 v1(73.79,72.39) ; v1(129.01,87.99) C57.2 C144.2 ; v1(62.87,94.74) 62.99,94.87 R229.2 ; R111.2 115.62,30.02 v1(115.32,29.72) ; J9.4 10.88,84.61 ; R106.1 v1(12.9,78.26) ; J9.6 6.54,79.06 ; J7.18 132.46,78.36 v1(133.79,77.03) ; C53.2 97.31,53.14 v1(97.97,53.14) ; C62.2 v1(17.35,21.36) ; C61.2 v1(19.02,27.71) ; J6.6 6.54,56.83 ; 85.47,15.37 v1(85.47,14.1) ; J6.5 6.54,75.5 ; J9.5 6.54,97.22 ; R141.2 v1(73.56,84.3) ; C196.2 v1(107.37,43.99) ; v1(18.41,21.18) 18.75,20.85 R149.2 ; R52.2 v1(34.92,68.5)
  TOP w0.635: 131.84,64.24 J7.6 130.73,63.12 ; J7.7 129.3,66.78 ; J7.7 129.3,64.54 ; J7.7 128.19,65.66 ; J7.7 130.42,65.66 ; 130.73,65.66 J7.8 ; J7.8 131.84,66.78 ; J7.8 131.84,64.54 ; J16.7 120.67,85.66 ; J16.7 120.67,81.64 ; J16.7 119.43,83.65 ; J7.20 132.96,80.9
  TOP w0.762: J6.4 10.92,62.61
  GND02 w0.635: J7.7 130.42,65.66 ; J7.7 128.19,65.66 ; J7.7 129.3,64.54 ; J7.7 129.3,66.78 ; M23.3 78.74,18.41 ; M23.3 78.74,16.99 ; M23.3 78.03,17.7 ; M23.3 79.45,17.7 ; M20.5 89.26,87.86 ; M20.5 89.97,87.15 ; M20.5 89.26,86.44 ; M20.5 88.55,87.15 ; M23.2 77.24,18.62 ; M23.2 75.81,18.62 ; M23.2 76.53,17.91 ; M23.2 76.53,19.33 ; 36.7,14.82 J4.1 ; J4.1 36.7,17.18 ; J4.1 37.88,16 ; J4.1 35.52,16 ; M22.4 9.33,103.26 ; M22.4 7.91,103.26 ; M22.4 8.62,103.97 ; M22.4 8.62,102.55 ; J7.20 132.96,80.9 ; J7.20 131.84,82.02 ; J7.20 131.84,79.78 ; J7.20 130.73,80.9 ; J1.4 115.14,10.44 ; J1.4 114.03,9.32 ; J1.4 114.03,11.56 ; J1.4 112.91,10.44 ; J16.3 114.5,109.02 ; J16.3 111.6,107.77 ; J16.3 117.39,107.77 ; 130.73,60.58 J7.4 ; J7.4 131.84,61.7 ; J7.4 131.84,59.46 ; J7.4 132.96,60.58 ; 8.27,101.66 8.27,102.37 ; 8.27,101.66 7.56,101.66 ; 8.27,101.66 8.27,100.95 ; 8.27,101.66 8.98,101.66 ; 4.59,106.28 M22.1 ; M22.1 5.3,106.99 ; M22.1 5.3,105.57 ; M22.1 6.01,106.28 ; J14.3 129.3,52.05 ; J14.3 130.42,50.93 ; J14.3 129.3,49.81 ; J14.3 128.19,50.93 ; M22.8 4,101 ; M22.8 4.71,100.29 ; M22.8 4,99.58 ; M22.8 3.28,100.29 ; 92.08,83.65 J16.6 ; J16.6 93.32,81.64 ; J16.6 94.57,83.65 ; J16.6 93.32,85.66 ; 7.16,99.73 M22.6 ; M22.6 6.45,100.44 ; M22.6 7.88,100.44 ; M22.6 7.16,101.15 ; J18.1 68.94,10.97 ; J18.1 68.2,10.05 ; J18.1 68.2,11.9 ; 31.91,8.58 M21.4 ; M21.4 32.62,9.3 ; M21.4 31.2,9.3 ; M21.4 31.91,10.01 ; 88.35,88.65 M20.6 ; M20.6 87.63,89.36 ; M20.6 88.35,90.08 ; M20.6 89.06,89.36 ; 130.73,58.04 J7.2 ; J7.2 131.84,56.92 ; J7.2 132.96,58.04 ; J7.2 131.84,59.16 ; J12.7 12.51,44.11 ; 6.54,79.66 J9.6 ; J9.6 8.42,81.54 ; J9.6 6.54,83.42 ; J9.6 4.66,81.54 ; 130.73,78.36 J7.18 ; J7.18 131.84,77.24 ; J7.18 131.84,79.48 ; J7.18 132.96,78.36 ; M20.8 83.92,90.08 ; M20.8 84.63,89.36 ; M20.8 83.21,89.36 ; M20.8 83.92,88.65 ; 96.6,107.77 J16.4 ; J16.4 102.39,107.77 ; J16.4 99.5,109.02 ; J16.4 99.5,106.53 ; J9.5 8.42,94.68 ; J9.5 6.54,96.56 ; J9.5 4.66,94.68 ; J9.5 6.54,92.8 ; S9.4 101.13,15.08 ; S9.4 99.75,13.7 ; S9.4 102.5,13.7 ; S9.4 101.13,12.33 ; 71.4,98.01 J34.5 ; J34.5 71.4,101.06 ; J34.5 72.57,99.54 ; J34.5 70.23,99.54 ; 56.98,74.93 J3.1 ; J3.1 58.17,76.11 ; J3.1 58.17,73.75 ; J3.1 59.35,74.93 ; 26.77,13.72 M21.8 ; M21.8 27.49,13.01 ; M21.8 28.2,13.72 ; M21.8 27.49,14.43 ; 78.03,23.96 M23.7 ; M23.7 78.74,23.25 ; M23.7 78.74,24.67 ; M23.7 79.45,23.96 ; M21.6 31.91,14.43 ; M21.6 31.91,13.01 ; M21.6 31.2,13.72 ; M21.6 32.62,13.72 ; J9.4 10.37,84.61 ; J9.4 8.13,84.61 ; J9.4 9.25,85.6 ; J9.4 9.25,83.62 ; 8.12,104.11 M22.3 ; M22.3 8.83,104.83 ; M22.3 8.12,105.54 ; M22.3 7.41,104.83 ; 4.66,72.68 J6.5 ; J6.5 6.54,74.56 ; J6.5 6.54,70.8 ; J6.5 8.42,72.68 ; 75.61,20.12 M23.1 ; M23.1 74.9,20.83 ; M23.1 76.32,20.83 ; M23.1 75.61,21.54 ; D3.2 75.51,10.34 ; D3.2 74.52,11.33 ; D3.2 73.53,10.34 ; D3.2 74.52,9.35 ; M23.5 81.87,21.54 ; M23.5 82.58,20.83 ; M23.5 81.16,20.83 ; M23.5 81.87,20.12 ; M20.7 86.84,90.28 ; M20.7 86.13,89.57 ; M20.7 86.13,90.99 ; M20.7 85.42,90.28 ; J7.6 132.96,63.12 ; J7.6 131.84,62 ; J7.6 130.73,63.12 ; J7.6 131.84,64.24 ; M23.6 80.95,23.76 ; M23.6 80.24,23.04 ; M23.6 80.95,22.33 ; M23.6 81.67,23.04 ; 6.23,50.68 J12.10 ; J12.10 9.83,50.68 ; J12.10 8.03,48.88 ; J12.10 8.03,52.49 ; 8.13,62.61 J6.4 ; J6.4 9.25,63.6 ; J6.4 10.37,62.61 ; J6.4 9.25,61.62 ; M21.2 27.49,10.01 ; M21.2 27.49,8.58 ; M21.2 26.77,9.3 ; M21.2 28.2,9.3 ; M21.3 30.41,8.38 ; M21.3 28.99,8.38 ; M21.3 29.7,9.09 ; 32.12,11.51 M21.5 ; M21.5 33.54,11.51 ; M21.5 32.83,10.8 ; M21.5 32.83,12.22 ; J16.7 121.92,83.65 ; J16.7 120.67,81.64 ; J16.7 119.43,83.65 ; J16.7 120.67,85.66 ; 25.86,11.51 M21.1 ; M21.1 27.28,11.51 ; M21.1 26.57,12.22 ; M21.1 26.57,10.8 ; 131.84,47.27 J14.2 ; J14.2 132.96,48.39 ; J14.2 131.84,49.51 ; J14.2 130.73,48.39 ; 80.95,17.91 M23.4 ; M23.4 80.24,18.62 ; M23.4 81.67,18.62 ; M23.4 80.95,19.33 ; 79.98,101.56 U9.3 ; U9.3 78.93,102.61 ; U9.3 79.98,103.67 ; U9.3 81.04,102.61 ; J14.1 130.42,48.39 ; J14.1 129.3,49.51 ; J14.1 129.3,47.27 ; J14.1 128.19,48.39 ; J26.21 45.45,103.52 ; J26.21 44.33,101.51 ; J26.21 46.57,101.51 ; J26.21 45.45,99.5 ; J12.11 8.03,39.35 ; J12.11 6.23,37.54 ; J12.11 9.83,37.54 ; J12.11 8.03,35.74 ; 4.66,59.54 J6.6 ; J6.6 6.54,57.66 ; J6.6 8.42,59.54 ; J6.6 6.54,61.42 ; M20.2 83.92,85.65 ; M20.2 83.92,84.22 ; M20.2 84.63,84.94 ; M20.2 83.21,84.94 ; J16.5 93.32,104.16 ; J16.5 93.32,100.14 ; J16.5 94.57,102.15 ; J16.5 92.08,102.15 ; J26.20 61.07,101.51 ; J26.20 59.95,103.52 ; J26.20 59.95,99.5 ; J26.20 58.83,101.51 ; J14.4 132.96,50.93 ; J14.4 131.84,52.05 ; J14.4 131.84,49.81 ; J14.4 130.73,50.93 ; 82.29,87.15 M20.1 ; M20.1 83,86.44 ; M20.1 83.71,87.15 ; M20.1 83,87.86 ; 81.38,9.35 LED1.2 ; LED1.2 82.5,10.47 ; LED1.2 82.5,8.23 ; LED1.2 83.62,9.35 ; 92.75,13.7 S9.3 ; S9.3 94.13,12.33 ; S9.3 95.5,13.7 ; S9.3 94.13,15.08 ; J26.22 61.07,107.47 ; J26.22 58.83,107.47 ; J26.22 59.95,105.72 ; J26.22 59.95,109.22 ; 120.67,100.14 J16.8 ; J16.8 121.92,102.15 ; J16.8 120.67,104.16 ; 85.42,84.02 M20.3 ; M20.3 86.84,84.02 ; M20.3 86.13,83.31 ; M20.3 86.13,84.73 ; M22.7 5.6,100.65 ; M22.7 6.31,99.94 ; M22.7 4.89,99.94 ; M22.7 5.6,99.23 ; 6.9,105.22 M22.2 ; M22.2 6.19,105.93 ; M22.2 7.62,105.93 ; M22.2 6.9,106.64 ; J5.1 81.41,33.95 ; J5.1 82.59,32.77 ; J5.1 81.41,31.58 ; J5.1 80.23,32.77 ; 28.99,14.64 M21.7 ; M21.7 29.7,15.35 ; M21.7 30.41,14.64 ; M21.7 29.7,13.93 ; 99.88,10.09 S9.2 ; S9.2 99.88,12.32 ; S9.2 98.76,11.2 ; S9.2 100.99,11.2 ; 87.63,84.94 M20.4 ; M20.4 89.06,84.94 ; M20.4 88.35,84.22 ; M20.4 88.35,85.65 ; J26.23 46.57,107.47 ; J26.23 45.45,109.22 ; J26.23 45.45,105.72 ; J26.23 44.33,107.47 ; J7.8 131.84,66.78 ; J7.8 131.84,64.54 ; J7.8 132.96,65.66 ; J7.8 130.73,65.66 ; 75.81,23.04 M23.8 ; M23.8 76.53,22.33 ; M23.8 77.24,23.04 ; M23.8 76.53,23.76 ; 9.05,40.61 J12.4 ; J12.4 10.03,39.63 ; J12.4 10.03,41.59 ; U7.2 115.64,50.75
  POWER03 w0.635: 92.75,13.7 S9.3 ; S9.3 94.13,12.33 ; S9.3 94.13,15.08 ; S9.3 95.5,13.7 ; 58.83,101.51 J26.20 ; J26.20 59.95,99.5 ; J26.20 59.95,103.52 ; J26.20 61.07,101.51 ; 32.12,11.51 M21.5 ; M21.5 32.83,12.22 ; M21.5 32.83,10.8 ; M21.5 33.54,11.51 ; J14.3 130.42,50.93 ; J14.3 129.3,49.81 ; J14.3 129.3,52.05 ; J14.3 128.19,50.93 ; LED1.2 82.5,10.47 ; LED1.2 83.62,9.35 ; LED1.2 81.38,9.35 ; LED1.2 82.5,8.23 ; M21.4 32.62,9.3 ; M21.4 31.91,10.01 ; M21.4 31.91,8.58 ; M21.4 31.2,9.3 ; J12.7 12.51,44.11 ; 6.54,57.66 J6.6 ; J6.6 4.66,59.54 ; J6.6 8.42,59.54 ; J6.6 6.54,61.42 ; 86.13,83.31 M20.3 ; M20.3 85.42,84.02 ; M20.3 86.84,84.02 ; M20.3 86.13,84.73 ; 101.13,12.33 S9.4 ; S9.4 99.75,13.7 ; S9.4 101.13,15.08 ; S9.4 102.5,13.7 ; M22.2 6.9,106.64 ; M22.2 6.19,105.93 ; M22.2 7.62,105.93 ; M22.2 6.9,105.22 ; J12.11 8.03,39.35 ; J12.11 6.23,37.54 ; J12.11 9.83,37.54 ; J12.11 8.03,35.74 ; J26.21 45.45,103.52 ; J26.21 45.45,99.5 ; J26.21 44.33,101.51 ; J26.21 46.57,101.51 ; 58.17,73.75 J3.1 ; J3.1 58.17,76.11 ; J3.1 59.35,74.93 ; J3.1 56.98,74.93 ; 27.49,8.58 M21.2 ; M21.2 26.77,9.3 ; M21.2 28.2,9.3 ; M21.2 27.49,10.01 ; 8.13,62.61 J6.4 ; J6.4 9.25,63.6 ; J6.4 9.25,61.62 ; J6.4 10.37,62.61 ; 6.54,92.8 J9.5 ; J9.5 4.66,94.68 ; J9.5 6.54,96.56 ; J9.5 8.42,94.68 ; U9.3 81.04,102.61 ; U9.3 79.98,101.56 ; U9.3 78.93,102.61 ; U9.3 79.98,103.67 ; 4.59,106.28 M22.1 ; M22.1 6.01,106.28 ; M22.1 5.3,106.99 ; M22.1 5.3,105.57 ; 99.88,10.09 S9.2 ; S9.2 99.88,12.32 ; S9.2 100.99,11.2 ; S9.2 98.76,11.2 ; M20.2 84.63,84.94 ; M20.2 83.92,84.22 ; M20.2 83.21,84.94 ; M20.2 83.92,85.65 ; M21.7 30.41,14.64 ; M21.7 29.7,13.93 ; M21.7 28.99,14.64 ; 93.32,100.14 J16.5 ; J16.5 93.32,104.16 ; J16.5 92.08,102.15 ; J16.5 94.57,102.15 ; J34.5 71.4,101.06 ; J34.5 70.23,99.54 ; J34.5 71.4,98.01 ; J34.5 72.57,99.54 ; M21.3 30.41,8.38 ; M21.3 29.7,9.09 ; M21.3 28.99,8.38 ; 83.92,88.65 M20.8 ; M20.8 83.21,89.36 ; M20.8 84.63,89.36 ; M20.8 83.92,90.08 ; 87.63,89.36 M20.6 ; M20.6 89.06,89.36 ; M20.6 88.35,88.65 ; M20.6 88.35,90.08 ; 6.45,100.44 M22.6 ; M22.6 7.16,99.73 ; M22.6 7.88,100.44 ; M22.6 7.16,101.15 ; J6.5 8.42,72.68 ; J6.5 6.54,74.56 ; J6.5 4.66,72.68 ; J6.5 6.54,70.8 ; J7.2 132.96,58.04 ; J7.2 131.84,56.92 ; J7.2 131.84,59.16 ; 83,86.44 M20.1 ; M20.1 83.71,87.15 ; M20.1 83,87.86 ; M20.1 82.29,87.15 ; U7.2 115.64,50.75 ; J7.4 132.96,60.58 ; J7.4 131.84,59.46 ; J7.4 131.84,61.7 ; J14.4 132.96,50.93 ; J14.4 130.73,50.93 ; J14.4 131.84,49.81 ; J14.4 131.84,52.05 ; 88.35,84.22 M20.4 ; M20.4 89.06,84.94 ; M20.4 88.35,85.65 ; M20.4 87.63,84.94 ; M20.7 86.84,90.28 ; M20.7 86.13,89.57 ; M20.7 85.42,90.28 ; M20.7 86.13,90.99 ; J7.6 131.84,64.24 ; J7.6 131.84,62 ; J7.6 132.96,63.12 ; 119.43,83.65 J16.7 ; J16.7 120.67,85.66 ; J16.7 121.92,83.65 ; J16.7 120.67,81.64 ; 68.94,10.97 J18.1 68.2,10.05 ; J9.6 6.54,83.42 ; J9.6 6.54,79.66 ; J9.6 8.42,81.54 ; J9.6 4.66,81.54 ; D3.2 75.51,10.34 ; D3.2 73.53,10.34 ; D3.2 74.52,9.35 ; J7.18 132.96,78.36 ; J7.18 131.84,77.24 ; J7.18 131.84,79.48 ; J16.6 93.32,85.66 ; J16.6 92.08,83.65 ; J16.6 93.32,81.64 ; J16.6 94.57,83.65 ; 7.56,101.66 8.27,101.66 ; 8.27,101.66 8.27,100.95 ; 8.27,101.66 8.27,102.37 ; 8.27,101.66 8.98,101.66 ; J26.23 46.57,107.47 ; J26.23 44.33,107.47 ; J26.23 45.45,109.22 ; J26.23 45.45,105.72 ; M22.4 8.62,103.97 ; M22.4 9.33,103.26 ; M22.4 8.62,102.55 ; M22.4 7.91,103.26 ; 8.03,48.88 J12.10 ; J12.10 8.03,52.49 ; J12.10 6.23,50.68 ; J14.1 130.42,48.39 ; J14.1 128.19,48.39 ; J14.1 129.3,49.51 ; J14.1 129.3,47.27 ; J14.2 131.84,49.51 ; J14.2 131.84,47.27 ; J14.2 130.73,48.39 ; J14.2 132.96,48.39 ; 9.05,40.61 J12.4 ; J12.4 10.03,41.59 ; J12.4 10.03,39.63 ; M22.3 8.12,105.54 ; M22.3 7.41,104.83 ; M22.3 8.83,104.83 ; M22.3 8.12,104.11 ; 9.25,83.62 J9.4 ; J9.4 8.13,84.61 ; J9.4 9.25,85.6 ; 120.67,100.14 J16.8 120.67,104.16 ; M22.8 4,101 ; M22.8 4,99.58 ; M22.8 4.71,100.29 ; M22.8 3.28,100.29 ; 26.57,10.8 M21.1 ; M21.1 25.86,11.51 ; M21.1 27.28,11.51 ; M21.1 26.57,12.22 ; 112.91,10.44 J1.4 ; J1.4 114.03,11.56 ; J1.4 115.14,10.44 ; J1.4 114.03,9.32 ; 131.84,64.54 J7.8 ; J7.8 131.84,66.78 ; J7.8 132.96,65.66 ; 31.2,13.72 M21.6 31.91,13.01 ; 111.6,107.77 J16.3 ; J16.3 117.39,107.77 ; J16.3 114.5,109.02 ; 5.6,99.23 M22.7 ; M22.7 5.6,100.65 ; M22.7 6.31,99.94 ; M22.7 4.89,99.94 ; 131.84,79.78 J7.20 ; J7.20 132.96,80.9 ; J7.20 131.84,82.02 ; J26.22 61.07,107.47 ; J26.22 58.83,107.47 ; J26.22 59.95,105.72 ; J26.22 59.95,109.22 ; 99.5,106.53 J16.4 ; J16.4 102.39,107.77 ; J16.4 96.6,107.77 ; J16.4 99.5,109.02 ; M20.5 89.97,87.15 ; M20.5 89.26,87.86 ; M20.5 89.26,86.44 ; M20.5 88.55,87.15 ; 26.77,13.72 M21.8 ; M21.8 27.49,14.43 ; M21.8 27.49,13.01 ; M21.8 28.2,13.72
  BOTTOM w0.254: S10.6 v1(72.39,79.88) ; S10.4 v1(74.48,84.4) ; v1(75.82,76.45) 75.49,76.78 S10.3 ; C146.2 v1(77.85,72.52)
  BOTTOM w0.305: C228.2 42.77,44.99 v2(42.59,45.17) ; v2(35.56,35.61) 35.43,35.74 C230.2 ; R46.1 36.82,58.12 v2(37.04,57.89)
  BOTTOM w0.381: C251.2 65.05,58.86 v2(64.38,59.54) ; 93.32,100.07 J16.5 ; J16.5 92,102.15 ; J16.5 93.32,104.23 ; J16.5 94.64,102.15 ; U9.3 79.98,103.74 ; U9.3 79.98,101.48 ; U9.3 78.85,102.61 ; U9.3 81.11,102.61 ; C216.2 39.01,60.66 v2(38.99,60.64) ; S9.2 101.07,11.2 ; S9.2 98.68,11.2 ; S9.2 99.88,10.01 ; S9.2 99.88,12.4 ; v2(37.04,57.23) 37.04,56.99 37.47,56.57 C203.2 ; C220.2 36.17,60.22 v2(36.59,60.64) ; J6.5 8.5,72.68 ; J6.5 4.58,72.68 ; J6.5 6.54,70.73 ; J6.5 6.54,74.64 ; J9.5 8.5,94.68 ; J9.5 6.54,92.73 ; J9.5 4.58,94.68 ; J9.5 6.54,96.64 ; J26.23 45.45,109.3 ; J26.23 46.64,107.47 ; J26.23 44.26,107.47 ; J26.23 45.45,105.64 ; C240.2 43.97,42.7 44.03,42.64 v2(44.58,42.64) ; J16.6 94.64,83.65 ; J16.6 92,83.65 ; J16.6 93.32,85.73 ; J16.6 93.32,81.57 ; J12.10 9.91,50.68 ; J12.10 8.03,52.56 ; J12.10 6.15,50.68 ; J12.10 8.03,48.8 ; C227.2 37.59,36.79 v2(37.81,36.57) ; 59.95,99.43 J26.20 ; J26.20 59.95,103.59 ; J26.20 61.14,101.51 ; J26.20 58.76,101.51 ; J9.6 6.54,83.5 ; J9.6 6.54,79.59 ; J9.6 8.5,81.54 ; J9.6 4.58,81.54 ; J7.7 130.5,65.66 ; J7.7 128.11,65.66 ; J7.7 129.3,66.86 ; J7.7 129.3,64.47 ; J12.11 8.03,39.42 ; J12.11 9.91,37.54 ; J12.11 8.03,35.66 ; J12.11 6.15,37.54 ; J9.4 9.25,85.68 ; J9.4 9.25,83.55 ; J9.4 8.06,84.61 ; J9.4 10.44,84.61 ; v2(34.21,47.21) 33.78,46.78 C258.2 ; 70.16,99.54 J34.5 ; J34.5 71.4,101.14 ; J34.5 72.65,99.54 ; J16.4 99.5,109.09 ; J16.4 102.47,107.77 ; J16.4 96.53,107.77 ; J16.4 99.5,106.45 ; C213.2 v2(44.6,59.84) ; C271.2 v2(39.12,63.58) ; 119.35,83.65 J16.7 ; J16.7 120.67,85.73 ; J16.7 121.99,83.65 ; J16.7 120.67,81.57 ; 114.03,9.25 J1.4 ; J1.4 114.03,11.64 ; J1.4 115.22,10.44 ; J1.4 112.83,10.44 ; C214.2 42.61,61.26 v2(42.31,61.57) ; 9.25,61.55 J6.4 ; J6.4 10.44,62.61 ; J6.4 8.06,62.61 ; J6.4 9.25,63.68 ; C106.2 41.55,38.24 v2(40.99,37.68) ; v2(57.25,56.95) 57.76,56.44 C248.2 ; 6.54,57.59 J6.6 ; J6.6 4.58,59.54 ; J6.6 6.54,61.5 ; J6.6 8.5,59.54 ; R71.1 37.41,40.87 v2(37.41,41.48) ; R160.2 v2(38.1,63.58) ; C233.2 38.3,41.91 v2(38.3,41.38) ; J4.1 37.96,16 ; J4.1 36.7,17.26 ; J4.1 35.45,16 ; J4.1 36.7,14.74 ; v2(32.99,37.68) 32.99,37.1 C229.2 ; C237.2 33.82,52.07 v2(33.81,52.06) ; v2(40.16,37.68) 40.54,38.05 C218.2 ; C219.2 40.11,61.69 v2(40.19,61.61) ; J7.8 131.84,66.86 ; J7.8 133.04,65.66 ; J7.8 131.84,64.47 ; J7.8 130.65,65.66 ; 81.41,31.51 J5.1 ; J5.1 80.15,32.77 ; J5.1 81.41,34.02 ; J5.1 82.66,32.77 ; 45.45,99.43 J26.21 ; J26.21 44.26,101.51 ; J26.21 46.64,101.51 ; J26.21 45.45,103.59 ; C34.2 42.42,39.19 v2(42.19,39.43) ; C73.2 85.8,64.59 85.47,64.26 v1(85.47,63.8) ; J26.22 59.95,109.3 ; J26.22 58.76,107.47 ; J26.22 61.14,107.47 ; J26.22 59.95,105.64 ; 133.23,63.12 J7.6 130.68,63.12 ; 41.31,55.84 41.32,55.82
  BOTTOM w0.508: D3.2 74.52,8.99 ; D3.2 75.9,10.34 ; D3.2 73.33,10.34 ; v1(79.76,82.42) 79.76,80.81 S10.5 ; J7.18 131.84,77.15 ; J7.18 130.6,78.36 ; J7.18 133.56,78.36 ; J7.20 131.84,82.02 ; J7.20 133.33,80.9 ; J7.20 130.63,80.9 ; J12.7 12.49,44.11 ; J18.1 68.2,9.91 ; 131.84,52.21 J14.4 133.38,50.93 ; 133.3,48.39 J14.2 131.84,47.23 ; LED1.2 82.5,8.1 ; S9.4 101.13,12.06 ; J12.4 8.94,40.61
  vias: v1(1.02,101.1) v1(1.02,99.82) v1(1.02,98.55) v1(1.02,97.27) v1(1.02,79.44) v1(1.02,78.17) v1(1.02,76.89) v1(1.02,75.62) v1(1.02,74.35) v1(1.02,57.79) v1(1.02,56.51) v1(1.02,55.24) v1(1.02,53.97) v1(1.02,52.69) v1(1.02,51.42) v1(1.02,50.15) v1(1.02,48.87) v1(1.02,47.6) v1(1.02,46.32) v1(1.02,45.05) v1(1.02,43.78) v1(1.02,42.5) v1(1.02,41.23) v1(1.02,39.96) v1(1.02,38.68) v1(1.02,37.41) v1(1.02,36.13) v1(1.02,34.86) v1(1.02,33.59) v1(1.02,32.31) v1(2.47,33.38) v1(3.81,97.28) v1(3.81,78.23) v1(3.81,75.69) v1(3.81,57.91) v1(3.81,55.37) v1(3.81,52.83) v1(3.81,50.29) v1(3.81,47.75) v1(3.81,45.21) v1(3.81,42.67) v1(3.81,40.13) v1(3.81,37.59) v1(3.81,35.05) v1(5.08,19.81) v1(5.13,17.03) v1(5.45,107.67) v1(6.35,55.37) v1(6.35,52.83) v1(6.35,47.75) v1(6.35,45.21) v1(6.35,42.67) v1(6.35,40.13) v1(6.35,35.05) v1(6.46,108.44) v1(6.5,17.03) v1(7.64,108.93) v1(7.62,78.23) v1(7.62,75.69) v1(7.62,19.81) v1(7.84,16.88) v1(8.9,109.1) v1(8.89,97.28) v1(8.89,55.37) v1(9.11,16.43) v1(10.19,109.1) v1(10.16,19.81) v1(10.16,17.91) v1(10.25,15.72) v1(10.54,56.52) v1(10.58,33.26) v1(11.2,14.76) v1(11.3,59.05) v1(11.43,97.28) v1(11.43,94.74) v1(11.43,37.59) v1(11.43,35.05) v1(11.49,109.1) v1(11.92,13.62) v1(12.06,62.23) v1(12.32,31.51) v1(12.29,17.65) v1(12.36,12.35) v1(12.52,11.01) v1(12.52,9.57) v1(12.52,8.13) v1(12.7,83.31) v1(12.7,19.81) v1(12.7,15.37) v1(12.78,109.1) v1(12.83,86.03) v1(13.08,63.25) v1(13.34,94.74) v1(13.41,34.01) v1(13.46,93.22) v1(13.47,29.71) v1(13.61,21.95) v1(13.74,51.59) v1(13.74,37.85) v1(13.79,8.13) v1(13.97,97.03) v1(14.08,109.1) v1(14.22,81.03) v1(14.22,45.72) v1(14.3,78.99) v1(14.35,64.39) v1(14.63,67.82) v1(14.73,88.9) v1(14.71,87.15) v1(14.73,8.13) v1(15.06,81.03) v1(15.06,78.99) v1(15.24,19.81) v1(15.37,108.21) v1(15.37,91.44) v1(15.37,90.55) v1(15.37,45.72) v1(15.37,40.06) v1(15.49,49.02) v1(15.75,85.34) v1(15.8,86.41) v1(16.33,9.14) v1(16.61,78.84) v1(16.67,108.21) v1(16.76,86.36) v1(16.76,85.34) v1(17.14,66.8) v1(17.6,9.14) v1(17.96,108.21) v1(18.87,9.14) v1(19.05,83.31) v1(19.05,81.91) v1(19.05,80.26) v1(19.05,78.74) v1(19.05,75.18) v1(19.05,73.91) v1(19.05,71.25) v1(19.05,10.92) v1(19.26,108.21) v1(19.43,59.44) v1(19.41,39.5) v1(19.47,60.4) v1(19.56,51.36) v1(20.15,9.14) v1(20.32,78.23) v1(20.32,76.96) v1(20.32,75.18) v1(20.32,73.91) v1(20.32,71.25) v1(20.55,108.21) v1(20.83,37.59) v1(20.83,35.05) v1(20.83,31.88) v1(21.08,49.71) v1(21.42,9.14) v1(21.59,78.23) v1(21.59,76.96) v1(21.62,47.29) v1(21.56,26.19) v1(21.59,10.92) v1(21.72,92.71) v1(21.85,108.21) v1(21.84,60.45) v1(21.84,59.44) v1(21.84,49.71) v1(22.1,73.91) v1(22.1,72.9) v1(22.1,72.01) v1(22.25,29.36) v1(22.38,47.29) v1(22.48,69.39) v1(22.48,68) v1(22.45,24.79) v1(22.69,9.14) v1(22.86,53.47) v1(23.14,108.21) v1(23.11,92.71) v1(23.11,91.82) v1(23.96,8.13) v1(24.1,15.98) v1(24.13,13.46) v1(24.13,10.92) v1(24.26,94.11) v1(24.26,92.71) v1(24.26,91.82) v1(25.23,8.13) v1(25.4,59.82) v1(25.43,26.19) v1(25.4,22.35) v1(25.4,18.54) v1(25.4,16) v1(25.53,72.9) v1(25.78,73.91) v1(26.04,56.64) v1(26.04,54.74) v1(26.04,52.83) v1(26.04,50.93) v1(26.04,49.02) v1(26.04,47.12) v1(26.04,45.21) v1(26.54,61.85) v1(26.5,8.13) v1(27.43,58.17) v1(27.81,45.85) v1(27.81,43.31) v1(27.81,41.4) v1(27.81,38.23) v1(27.81,35.69) v1(28.04,74.19) v1(27.99,23.62) v1(28.17,84.58) v1(28.32,63.5) v1(28.57,59.18) v1(28.57,33.15) v1(28.7,69.34) v1(28.8,74.19) v1(28.88,82.91) v1(29.02,88.04) v1(29.54,75.87) v1(29.57,75.03) v1(29.57,74.19) v1(29.84,60.45) v1(29.84,31.88) v1(30.86,70.87) v1(31.11,61.72) v1(31.11,30.61) v1(31.61,88.04) v1(31.75,23.62) v1(31.88,69.72) v1(32.38,29.34) v1(32.86,8.13) v1(33.02,21.08) v1(33.81,28.85) v1(34.01,84.63) v1(34.09,82.85) v1(34.13,8.13) v1(34.16,72.14) v1(34.29,23.62) v1(35.25,88.04) v1(35.4,8.13) v1(35.56,21.08) v1(35.56,18.54) v1(35.56,12.19) v1(35.56,9.65) v1(36.7,72.82) v1(36.7,72.06) v1(36.68,8.13) v1(36.83,23.62) v1(37.95,8.13) v1(37.96,88.04) v1(37.97,77.09) v1(37.97,76.07) v1(38.1,21.08) v1(38.1,18.54) v1(38.1,14.73) v1(38.1,12.19) v1(38.1,9.65) v1(38.92,88.01) v1(39.19,84.76) v1(39.24,72.75) v1(39.24,71.98) v1(39.22,8.13) v1(39.37,23.62) v1(39.5,76.07) v1(39.75,80.14) v1(40.31,77.44) v1(40.39,68.71) v1(40.49,8.13) v1(40.64,21.08) v1(40.64,18.54) v1(40.64,14.73) v1(40.64,12.19) v1(40.64,9.65) v1(40.89,80.14) v1(41.53,76.07) v1(41.58,77.44) v1(41.76,8.13) v1(41.91,23.62) v1(42.8,23.62) v1(43.03,8.13) v1(43.18,12.19) v1(43.18,9.65) v1(43.43,63.5) v1(43.86,109.1) v1(44.3,8.13) v1(44.45,98.55) v1(44.45,96.01) v1(44.45,89.66) v1(44.62,92.38) v1(44.7,23.62) v1(45.58,8.13) v1(45.72,98.55) v1(45.72,96.01) v1(45.72,89.66) v1(45.72,87.12) v1(45.72,65.79) v1(45.72,9.65) v1(45.82,92.38) v1(46.05,94.5) v1(46.33,38.07) v1(46.74,44.96) v1(46.76,68.2) v1(46.85,8.13) v1(46.99,87.12) v1(47.12,40.77) v1(47.12,28.58) v1(47.24,23.62) v1(47.49,108.08) v1(47.5,105.66) v1(47.55,38.07) v1(47.73,84.61) v1(48.12,8.13) v1(48.16,41.73) v1(48.26,9.65) v1(48.74,40.54) v1(48.72,38.07) v1(48.78,108.08) v1(48.84,67.74) v1(49.02,74.68) v1(49.2,42.75) v1(49.39,8.13) v1(49.45,82.96) v1(49.68,41.38) v1(49.91,74.68) v1(49.89,67.56) v1(49.96,65.68) v1(49.99,38.1) v1(50.08,108.08) v1(50.29,105.66) v1(50.29,84.58) v1(50.42,28.58) v1(50.66,8.13) v1(50.8,9.65) v1(51.26,23.49) v1(51.37,108.08) v1(51.82,82.96) v1(51.94,65.23) v1(51.93,8.13) v1(52.67,108.08) v1(52.96,105.66) v1(53.21,9.14) v1(53.34,80.77) v1(53.47,23.49) v1(53.59,13.08) v1(53.87,28.32) v1(53.96,108.08) v1(53.98,10.29) v1(54.23,17.4) v1(54.46,68.91) v1(54.48,9.14) v1(54.61,79.5) v1(54.74,69.85) v1(54.99,68.07) v1(55.12,75.82) v1(55.14,29.59) v1(55.24,72.52) v1(55.58,108.08) v1(55.75,9.14) v1(55.75,18.54) v1(55.88,78.23) v1(55.88,20.19) v1(56.13,105.66) v1(56.26,70.48) v1(56.39,71.75) v1(56.41,30.86) v1(56.52,10.29) v1(56.64,68.45) v1(56.9,20.19) v1(56.9,18.54) v1(57.02,9.14) v1(57.1,108.13) v1(57.12,70.05) v1(57.28,67.82) v1(57.53,71.12) v1(57.53,69.22) v1(57.68,32.13) v1(57.66,18.54) v1(57.78,20.19) v1(58.1,109.1) v1(58.33,17) v1(58.29,9.14) v1(58.95,33.4) v1(59.09,17) v1(59.31,71.12) v1(59.56,9.14) v1(59.72,70.05) v1(59.69,67.82) v1(59.69,10.29) v1(59.85,17) v1(60.22,34.67) v1(60.45,66.67) v1(60.58,72.9) v1(60.58,71.25) v1(60.58,68.71) v1(60.61,17) v1(60.83,8.64) v1(60.96,93.47) v1(60.96,90.93) v1(60.96,87.76) v1(61.47,100.2) v1(61.49,35.94) v1(61.98,109.1) v1(61.98,107.61) v1(62.11,8.13) v1(62.23,88.39) v1(62.23,85.85) v1(62.23,10.29) v1(62.57,106.19) v1(62.76,37.21) v1(63.04,90.27) v1(63.38,8.13) v1(63.75,105.28) v1(63.88,18.54) v1(64.65,8.13) v1(64.77,88.39) v1(64.77,85.85) v1(64.77,83.31) v1(65.02,25.91) v1(65.15,27.56) v1(65.51,16.66) v1(65.91,25.91) v1(65.92,8.13) v1(66.04,27.56) v1(66.65,18.57) v1(66.8,25.91) v1(66.93,27.56) v1(67.19,8.13) v1(67.6,24.36) v1(68.05,98.5) v1(68.38,24.38) v1(68.46,8.13) v1(68.81,20.5) v1(68.83,18.54) v1(68.96,80.14) v1(69.16,24.38) v1(69.47,64.9) v1(69.74,8.13) v1(69.85,103.63) v1(69.95,24.38) v1(70.1,108.2) v1(70.21,10.77) v1(70.36,14.61) v1(70.48,16.64) v1(71.01,8.13) v1(71.15,33.55) v1(71.98,65.35) v1(72.26,105.54) v1(72.28,8.13) v1(72.39,103.63) v1(72.39,88.39) v1(72.39,87.12) v1(72.39,66.98) v1(72.39,36.32) v1(72.85,30.15) v1(73.36,42.7) v1(73.55,8.13) v1(73.79,39.75) v1(74.3,43.69) v1(74.3,36.32) v1(74.55,86.23) v1(74.74,62.84) v1(74.82,8.13) v1(74.93,106.17) v1(74.93,103.63) v1(74.93,101.09) v1(74.94,45.47) v1(75.1,108.21) v1(75.18,73.15) v1(75.82,44.58) v1(75.9,90.93) v1(75.95,41.4) v1(76,63.65) v1(76.07,28.07) v1(76.09,8.13) v1(76.33,25.65) v1(76.39,108.21) v1(77.22,40.01) v1(77.34,43.56) v1(77.37,8.13) v1(77.47,106.17) v1(77.47,103.63) v1(77.47,85.85) v1(77.69,108.21) v1(77.72,36.45) v1(78.49,87.88) v1(78.61,25.78) v1(78.64,8.13) v1(78.74,85.85) v1(78.66,60.71) v1(78.99,108.21) v1(79.15,40.06) v1(79.12,38.73) v1(79.76,43.94) v1(79.88,74.55) v1(79.88,73.41) v1(80.01,106.17) v1(80.01,88.39) v1(80.01,85.85) v1(80.01,61.72) v1(80.01,35.05) v1(80.28,108.21) v1(80.26,38.18) v1(80.52,90.04) v1(80.85,60.81) v1(80.77,36.96) v1(81.58,108.21) v1(81.81,38.28) v1(82.17,43.94) v1(83.06,109.09) v1(83.44,60.96) v1(83.36,38.3) v1(83.57,69.47) v1(83.57,62.1) v1(83.82,92.2) v1(83.82,35.05) v1(83.82,29.97) v1(84.05,42.8) v1(84.05,39.5) v1(84.07,41.4) v1(84.18,109.1) v1(84.28,53.8) v1(85.09,106.17) v1(85.09,81.79) v1(85.47,109.1) v1(85.85,60.83) v1(86.35,53.82) v1(86.36,92.2) v1(86.36,19.81) v1(86.49,106.07) v1(86.52,9.02) v1(86.61,69.39) v1(86.61,68.12) v1(86.77,109.1) v1(86.82,107.95) v1(87.12,60.83) v1(87.63,103.63) v1(87.78,109.17) v1(87.79,9.02) v1(87.88,69.39) v1(87.88,68.12) v1(87.88,66.73) v1(87.91,26.37) v1(88.39,11.99) v1(88.6,103) v1(88.9,97.28) v1(88.9,96.01) v1(88.9,94.74) v1(88.9,93.47) v1(88.9,92.2) v1(88.9,19.81) v1(89.06,9.02) v1(89.15,69.39) v1(89.15,68.12) v1(89.15,66.73) v1(90.17,102.36) v1(90.17,101.09) v1(90.17,99.82) v1(90.17,98.55) v1(90.17,97.28) v1(90.17,96.01) v1(90.17,94.74) v1(90.17,93.47) v1(90.17,92.2) v1(90.17,90.93) v1(90.17,84.58) v1(90.17,83.31) v1(90.17,26.37) v1(90.33,9.02) v1(90.81,14.58) v1(90.93,55.3) v1(90.93,54.28) v1(91.29,12.07) v1(91.44,88.39) v1(91.44,87.12) v1(91.44,19.81) v1(91.63,102.81) v1(91.63,101.54) v1(91.63,100.27) v1(91.63,99) v1(91.63,97.73) v1(91.61,9.02) v1(91.69,70.46) v1(92.01,90.49) v1(92.08,53.47) v1(92.49,99.38) v1(92.49,98.11) v1(92.49,96.84) v1(92.49,95.57) v1(92.52,93.03) v1(92.52,91.76) v1(92.71,88.39) v1(92.71,87.12) v1(92.79,109.22) v1(92.88,9.02) v1(93.25,90.49) v1(93.56,109.07) v1(93.66,104.74) v1(93.76,99.38) v1(93.76,98.11) v1(93.76,96.84) v1(93.76,95.57) v1(93.76,93.03) v1(93.76,91.76) v1(93.98,19.81) v1(94.06,107.2) v1(94.06,105.93) v1(94.52,94.55) v1(94.55,109.1) v1(94.93,107.25) v1(94.93,105.98) v1(94.93,104.71) v1(95.03,102.81) v1(95.03,101.54) v1(95.03,99.63) v1(95.03,97.73) v1(95.03,96.46) v1(95.03,92.65) v1(95.25,28.7) v1(95.25,26.16) v1(95.17,8.13) v1(95.38,73.2) v1(95.38,71.42) v1(95.5,76.33) v1(95.5,74.85) v1(95.63,65.33) v1(95.63,64.19) v1(95.85,109.1) v1(95.96,60.27) v1(96.01,58.06) v1(96.14,107.04) v1(96.2,105.98) v1(96.2,104.71) v1(96.3,103.44) v1(96.3,102.17) v1(96.3,100.27) v1(96.3,98.36) v1(96.3,95.82) v1(96.43,94.55) v1(96.44,8.13) v1(96.52,42.67) v1(96.52,38.23) v1(96.52,19.81) v1(96.72,60.27) v1(96.77,58.06) v1(96.93,102.81) v1(96.93,101.54) v1(96.93,99.63) v1(96.93,97.73) v1(96.93,96.46) v1(97.15,109.1) v1(97.34,105.98) v1(97.28,74.85) v1(97.28,73.2) v1(97.28,71.42) v1(97.28,70.03) v1(97.28,67.36) v1(97.28,65.33) v1(97.28,63.3) v1(97.41,77.39) v1(97.43,21.36) v1(97.57,104.71) v1(97.57,103.82) v1(97.6,94.26) v1(97.71,8.13) v1(97.79,55.12) v1(97.79,54.23) v1(97.79,28.7) v1(97.79,26.16) v1(97.95,105.4) v1(97.95,103.06) v1(97.95,97.35) v1(97.94,12.78) v1(97.94,10.01) v1(98.04,61.21) v1(98.33,96.2) v1(98.42,38.23) v1(98.49,106.25) v1(98.58,102.6) v1(98.58,101.41) v1(98.58,100.39) v1(98.58,99.38) v1(98.58,98.24) v1(98.81,77.39) v1(98.97,105.6) v1(98.98,8.13) v1(99.09,97.6) v1(99.06,61.21) v1(99.06,42.67) v1(99.06,19.81) v1(99.57,18.92) v1(99.98,88.33) v1(100.11,105.6) v1(100.11,97.6) v1(100.33,77.39) v1(100.33,74.98) v1(100.33,73.2) v1(100.33,70.92) v1(100.33,69.01) v1(100.33,67.23) v1(100.33,65.33) v1(100.33,63.3) v1(100.33,61.26) v1(100.25,8.13) v1(100.36,102.55) v1(100.36,101.54) v1(100.36,100.39) v1(100.49,99.51) v1(100.46,83.69) v1(100.46,82.55) v1(100.67,33.52) v1(100.87,106.11) v1(100.87,105.22) v1(100.87,97.6) v1(101.03,84.53) v1(100.97,38.23) v1(101.16,85.29) v1(101.3,34.15) v1(101.41,80.54) v1(101.51,103.06) v1(101.51,102.17) v1(101.51,101.16) v1(101.63,96.71) v1(101.6,42.67) v1(101.6,28.7) v1(101.6,26.16) v1(101.76,97.6) v1(101.85,63.37) v1(101.85,61.09) v1(102.05,106.63) v1(102.02,84.42) v1(101.96,21.29) v1(102.11,77.39) v1(102.11,74.98) v1(102.11,73.2) v1(102.11,70.92) v1(102.11,69.01) v1(102.11,67.23) v1(102.11,65.33) v1(102.06,33.39) v1(102.34,109.1) v1(102.4,85.23) v1(102.65,101.16) v1(102.78,103.06) v1(102.78,102.17) v1(102.78,97.6) v1(102.8,8.13) v1(102.85,104.64) v1(102.85,103.87) v1(102.9,96.84) v1(102.87,38.23) v1(102.87,11.56) v1(102.87,9.65) v1(103.03,80.58) v1(103.21,106.62) v1(103.39,107.96) v1(103.38,58.17) v1(103.35,57.3) v1(103.54,84.52) v1(103.63,109.1) v1(103.63,77.85) v1(103.63,76.83) v1(103.79,97.6) v1(104.05,96.84) v1(104.05,85.26) v1(104.07,8.13) v1(104.3,80.58) v1(104.52,17.14) v1(104.52,16.13) v1(104.55,84.52) v1(104.68,97.6) v1(104.78,38.23) v1(104.93,109.1) v1(104.91,96.86) v1(105.34,8.13) v1(105.41,27.43) v1(105.41,26.16) v1(105.41,21.11) v1(105.41,14.99) v1(105.57,106.87) v1(105.57,105.98) v1(105.57,104.64) v1(105.57,103.82) v1(105.57,102.55) v1(105.57,101.28) v1(105.57,80.58) v1(105.7,84.52) v1(106.23,109.1) v1(106.33,87.69) v1(106.46,100.27) v1(106.55,77.98) v1(106.55,76.83) v1(106.61,8.13) v1(106.66,101.92) v1(106.71,99.38) v1(106.71,98.36) v1(106.71,86.04) v1(106.71,84.52) v1(106.84,80.58) v1(107.17,101.16) v1(107.52,109.1) v1(107.47,107.76) v1(107.47,106.49) v1(107.55,103.82) v1(107.57,100.33) v1(107.88,8.13) v1(107.98,101.92) v1(107.95,28.7) v1(108.11,80.58) v1(108.32,107) v1(108.32,105.47) v1(108.32,104.33) v1(108.32,101.16) v1(108.36,87.08) v1(108.36,86.04) v1(108.49,99.38) v1(108.49,93.66) v1(108.49,92.9) v1(108.49,92.14) v1(108.62,107.89) v1(108.74,84.52) v1(108.82,109.1) v1(108.82,98.39) v1(108.8,97.04) v1(108.95,101.92) v1(109.15,8.13) v1(109.28,93.67) v1(109.28,92.91) v1(109.28,92.15) v1(109.25,87.11) v1(109.25,86.04) v1(109.38,80.58) v1(109.6,32.64) v1(109.76,107.89) v1(110.04,92.91) v1(110.04,92.15) v1(110.12,109.1) v1(110.35,105.09) v1(110.35,104.08) v1(110.35,103.06) v1(110.43,8.13) v1(110.52,102.3) v1(110.52,101.28) v1(110.52,100.52) v1(110.55,97.96) v1(110.52,96.84) v1(110.49,13.46) v1(110.65,87.14) v1(110.65,86.04) v1(110.62,80.64) v1(110.74,50.95) v1(111.05,23.55) v1(111.28,102.68) v1(111.28,100.52) v1(111.42,109.1) v1(111.41,101.54) v1(111.44,97.96) v1(111.41,84.27) v1(111.62,105.22) v1(111.62,104.2) v1(111.7,8.13) v1(111.79,87.14) v1(111.79,86.04) v1(111.93,62.86) v1(111.89,58.06) v1(112.05,103.06) v1(112.05,100.52) v1(112.27,80.52) v1(112.34,79.4) v1(112.43,84.27) v1(112.37,67.23) v1(112.39,61.85) v1(112.55,64.14) v1(112.63,104.2) v1(112.55,101.54) v1(112.55,97.98) v1(112.55,96.97) v1(112.81,100.52) v1(112.81,61.21) v1(112.94,103.06) v1(112.94,88.08) v1(112.94,87.19) v1(112.94,86.04) v1(113.03,22.61) v1(112.97,8.13) v1(113.08,66.88) v1(113.06,65.96) v1(113.13,65) v1(113.17,105.14) v1(113.32,98.49) v1(113.28,72.01) v1(113.44,84.27) v1(113.57,102.55) v1(113.57,101.66) v1(113.57,100.52) v1(113.7,96.97) v1(113.95,88.08) v1(113.95,87.19) v1(113.95,86.04) v1(114.05,80.52) v1(114.05,79.38) v1(114.05,8.13) v1(114.3,13.46) v1(114.54,89.4) v1(114.46,84.27) v1(114.51,65.78) v1(114.51,64.51) v1(114.53,24.92) v1(114.6,57.81) v1(114.79,96.97) v1(114.97,88.08) v1(114.97,87.19) v1(114.97,85.92) v1(115.19,89.85) v1(115.35,102.55) v1(115.35,101.54) v1(115.26,91.25) v1(115.38,100.66) v1(115.43,99.89) v1(115.43,99) v1(115.51,9.14) v1(115.61,85.48) v1(115.6,80.58) v1(115.62,79.38) v1(115.78,105.19) v1(115.78,65.78) v1(115.78,64.51) v1(115.94,96.97) v1(115.9,57.81) v1(115.96,84.62) v1(116.11,94.55) v1(116.19,102.93) v1(116.53,104.85) v1(116.49,103.82) v1(116.62,93.41) v1(116.62,91.89) v1(116.62,90.62) v1(116.7,87.44) v1(116.72,83.35) v1(116.72,82.08) v1(116.84,13.46) v1(116.78,9.14) v1(116.95,65.78) v1(116.95,64.51) v1(116.95,95.95) v1(117.08,96.97) v1(117.33,86.81) v1(117.46,103.06) v1(117.47,50.29) v1(117.47,49.02) v1(117.47,47.75) v1(117.47,45.21) v1(117.47,42.67) v1(117.71,107.25) v1(117.89,105.22) v1(117.89,104.08) v1(118.05,93.55) v1(118.05,92.15) v1(118.02,91.38) v1(118.02,90.36) v1(118.02,88.2) v1(118.09,96.08) v1(118.12,85.97) v1(118.12,84.7) v1(118.12,83.43) v1(118.14,80.58) v1(118.08,39.37) v1(118.11,38.23) v1(118.11,36.96) v1(118.05,9.14) v1(118.16,108.21) v1(118.22,95.31) v1(118.18,82.07) v1(118.6,102.93) v1(118.94,91.64) v1(119.16,107.25) v1(119.16,105.22) v1(119.16,104.08) v1(119.33,85.67) v1(119.32,81.74) v1(119.38,67.31) v1(119.38,63.37) v1(119.38,61.47) v1(119.38,50.29) v1(119.38,49.02) v1(119.38,47.75) v1(119.38,45.21) v1(119.38,42.67) v1(119.38,38.23) v1(119.45,108.21) v1(119.51,9.14) v1(119.62,100.01) v1(119.62,98.74) v1(119.62,97.85) v1(119.62,80.58) v1(119.79,90.62) v1(119.79,87.44) v1(119.79,86.42) v1(120.02,69.85) v1(120.13,91.89) v1(120.25,104.84) v1(120.43,107.25) v1(120.4,73.28) v1(120.4,70.87) v1(120.63,99.12) v1(120.75,108.21) v1(120.76,97.85) v1(120.94,91.4) v1(120.85,9.02) v1(121.03,59.69) v1(121.03,57.53) v1(121.14,90.16) v1(121.07,88.35) v1(121.12,86.75) v1(121.52,107.25) v1(121.65,100.14) v1(121.85,106.24) v1(121.78,99) v1(121.78,97.85) v1(121.78,96.71) v1(121.79,95.63) v1(121.79,94.74) v1(121.92,93.85) v1(121.92,50.29) v1(121.92,49.02) v1(121.92,47.75) v1(121.92,45.21) v1(121.92,42.67) v1(121.92,14.73) v1(121.92,13.46) v1(121.92,12.19) v1(121.92,10.29) v1(122.05,108.21) v1(122.05,59.69) v1(122.05,57.53) v1(122.12,9.02) v1(122.29,107.25) v1(122.3,62.36) v1(122.3,61.34) v1(122.48,105.6) v1(123.34,108.21) v1(123.32,29.01) v1(123.38,107.39) v1(123.39,9.02) v1(123.68,106.11) v1(123.68,104.84) v1(123.68,103.57) v1(123.68,102.3) v1(123.68,101.03) v1(123.68,99.76) v1(123.68,98.49) v1(123.68,97.22) v1(124.08,89.03) v1(124.41,8.13) v1(124.46,50.29) v1(124.46,49.02) v1(124.46,47.75) v1(124.46,45.21) v1(124.46,42.67) v1(124.46,40.13) v1(124.46,14.73) v1(124.46,13.46) v1(124.46,12.19) v1(124.46,10.29) v1(124.64,108.21) v1(124.84,96.65) v1(124.84,95.63) v1(125.22,62.36) v1(125.22,61.34) v1(125.6,100.96) v1(125.6,99.82) v1(125.6,98.55) v1(125.6,69.85) v1(125.68,109.1) v1(125.68,107.7) v1(125.68,106.3) v1(125.68,104.91) v1(125.68,103.51) v1(125.68,102.11) v1(125.68,11.01) v1(125.68,9.57) v1(125.68,8.13) v1(125.83,12.35) v1(125.86,96.65) v1(125.86,95.63) v1(125.86,15.49) v1(125.98,13.72) v1(126.62,69.85) v1(127,50.29) v1(127,48.9) v1(127,47.75) v1(127,45.21) v1(127,42.67) v1(127,40.13) v1(127,16.51) v1(127,14.76) v1(127.95,15.72) v1(128.78,18.54) v1(129.41,17.78) v1(129.54,45.21) v1(129.54,42.67) v1(129.67,29.01) v1(129.77,40.16) v1(130.02,34.95) v1(130.12,37.69) v1(130.1,32.46) v1(130.36,16.88) v1(130.56,19.69) v1(130.81,18.16) v1(131.7,17.03) v1(132.08,45.21) v1(132.08,42.67) v1(132.08,40.13) v1(132.08,37.59) v1(132.08,35.05) v1(132.08,32.51) v1(132.08,29.97) v1(132.08,27.43) v1(132.08,24.89) v1(133.07,17.03) v1(133.76,80.04) v1(134.44,17.03) v1(134.62,52.83) v1(134.62,50.29) v1(134.62,47.75) v1(134.62,45.21) v1(134.62,42.67) v1(134.62,37.59) v1(134.62,35.05) v1(134.62,32.51) v1(134.62,29.97) v1(134.62,27.43) v1(134.62,24.89) v1(134.75,39.67) v1(135.38,76.58) v1(135.81,17.03) v1(136.02,92.58) v1(137.18,93.55) v1(137.18,92.27) v1(137.18,90.99) v1(137.18,89.72) v1(137.18,88.44) v1(137.18,87.17) v1(137.18,85.89) v1(137.18,84.62) v1(137.18,83.34) v1(137.18,82.07) v1(137.18,80.79) v1(137.18,79.52) v1(137.18,78.24) v1(137.18,76.97) v1(137.18,75.69) v1(137.18,74.42) v1(137.18,73.14) v1(137.18,71.87) v1(137.18,70.59) v1(137.18,69.31) v1(137.18,68.04) v1(137.18,66.76) v1(137.18,65.49) v1(137.18,64.21) v1(137.18,62.94) v1(137.18,61.66) v1(137.18,60.39) v1(137.18,59.11) v1(137.18,57.84) v1(137.18,56.56) v1(137.18,55.29) v1(137.18,54.01) v1(137.18,52.74) v1(137.18,51.46) v1(137.18,50.19) v1(137.18,48.91) v1(137.18,47.63) v1(137.18,46.36) v1(137.18,45.08) v1(137.18,43.81) v1(137.18,42.53) v1(137.18,41.26) v1(137.18,39.98) v1(137.18,38.71) v1(137.18,37.43) v1(137.18,36.16) v1(137.18,34.88) v1(137.18,33.61) v1(137.18,32.33) v1(137.18,31.06) v1(137.18,29.78) v1(137.18,28.51) v1(137.18,27.23) v1(137.18,25.95) v1(137.18,24.68) v1(137.16,23.62) v1(137.16,18.03) v1(137.18,17.03) v1(137.29,19.05) v1(137.36,22.4) v1(137.39,20.88) v2(31.78,62.44) v2(33.1,63.48) v2(34.01,62.64) v2(35.78,51.96) v2(40.58,43.44) v2(41.15,47.24) v2(41.4,42.64) v2(41.53,40.31) v2(41.83,50.86) v2(41.78,48.95) v2(42.04,47.5) v2(42.21,57.57) v2(42.16,56.77) v2(42.32,63.6) v2(42.87,52.08) v2(42.98,49.48) v2(43.1,57.57) v2(43.18,47.12) v2(43.2,41.33) v2(43.2,40.7) v2(43.51,58.78) v2(43.76,52.08) v2(43.84,47.73) v2(43.79,39.43) v2(44.42,50.42) v2(44.83,48.87) v2(45.47,49.4) v2(45.54,45.14) v2(45.59,41.4) v2(45.92,54.38) v2(45.95,53.72) v2(46,50.39) v2(46,48.92) v2(46.25,52.07) v2(46.74,49.66) v2(46.99,42.67) v2(47.37,51.03) v2(47.96,50.44) v2(49.17,54.05) v2(49.89,53.37) v2(56.13,56.92) v2(60.45,64.64) v2(62.56,57.86) v2(64.03,38.48) v2(64.38,48.34) v2(66.6,51.08) v2(66.65,50.47) v2(66.57,49) v2(71.2,41.1) v2(71.2,38.23) v2(71.32,64.54) v2(72.26,41.07) v2(72.39,38.23) v2(101.35,29.39)
